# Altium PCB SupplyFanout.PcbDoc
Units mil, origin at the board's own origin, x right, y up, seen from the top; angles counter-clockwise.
Board outline 8000 x 4500 mil, 6 copper layers (Top Layer, Int1 GND, Int2 PWR, Int3 GND, Int4 PWR, Bottom Layer), stack 61.068 mil thick; 132 components, 68 nets, 469 pads, 69 vias.
Unrouted connection lines stored in the file: 26.
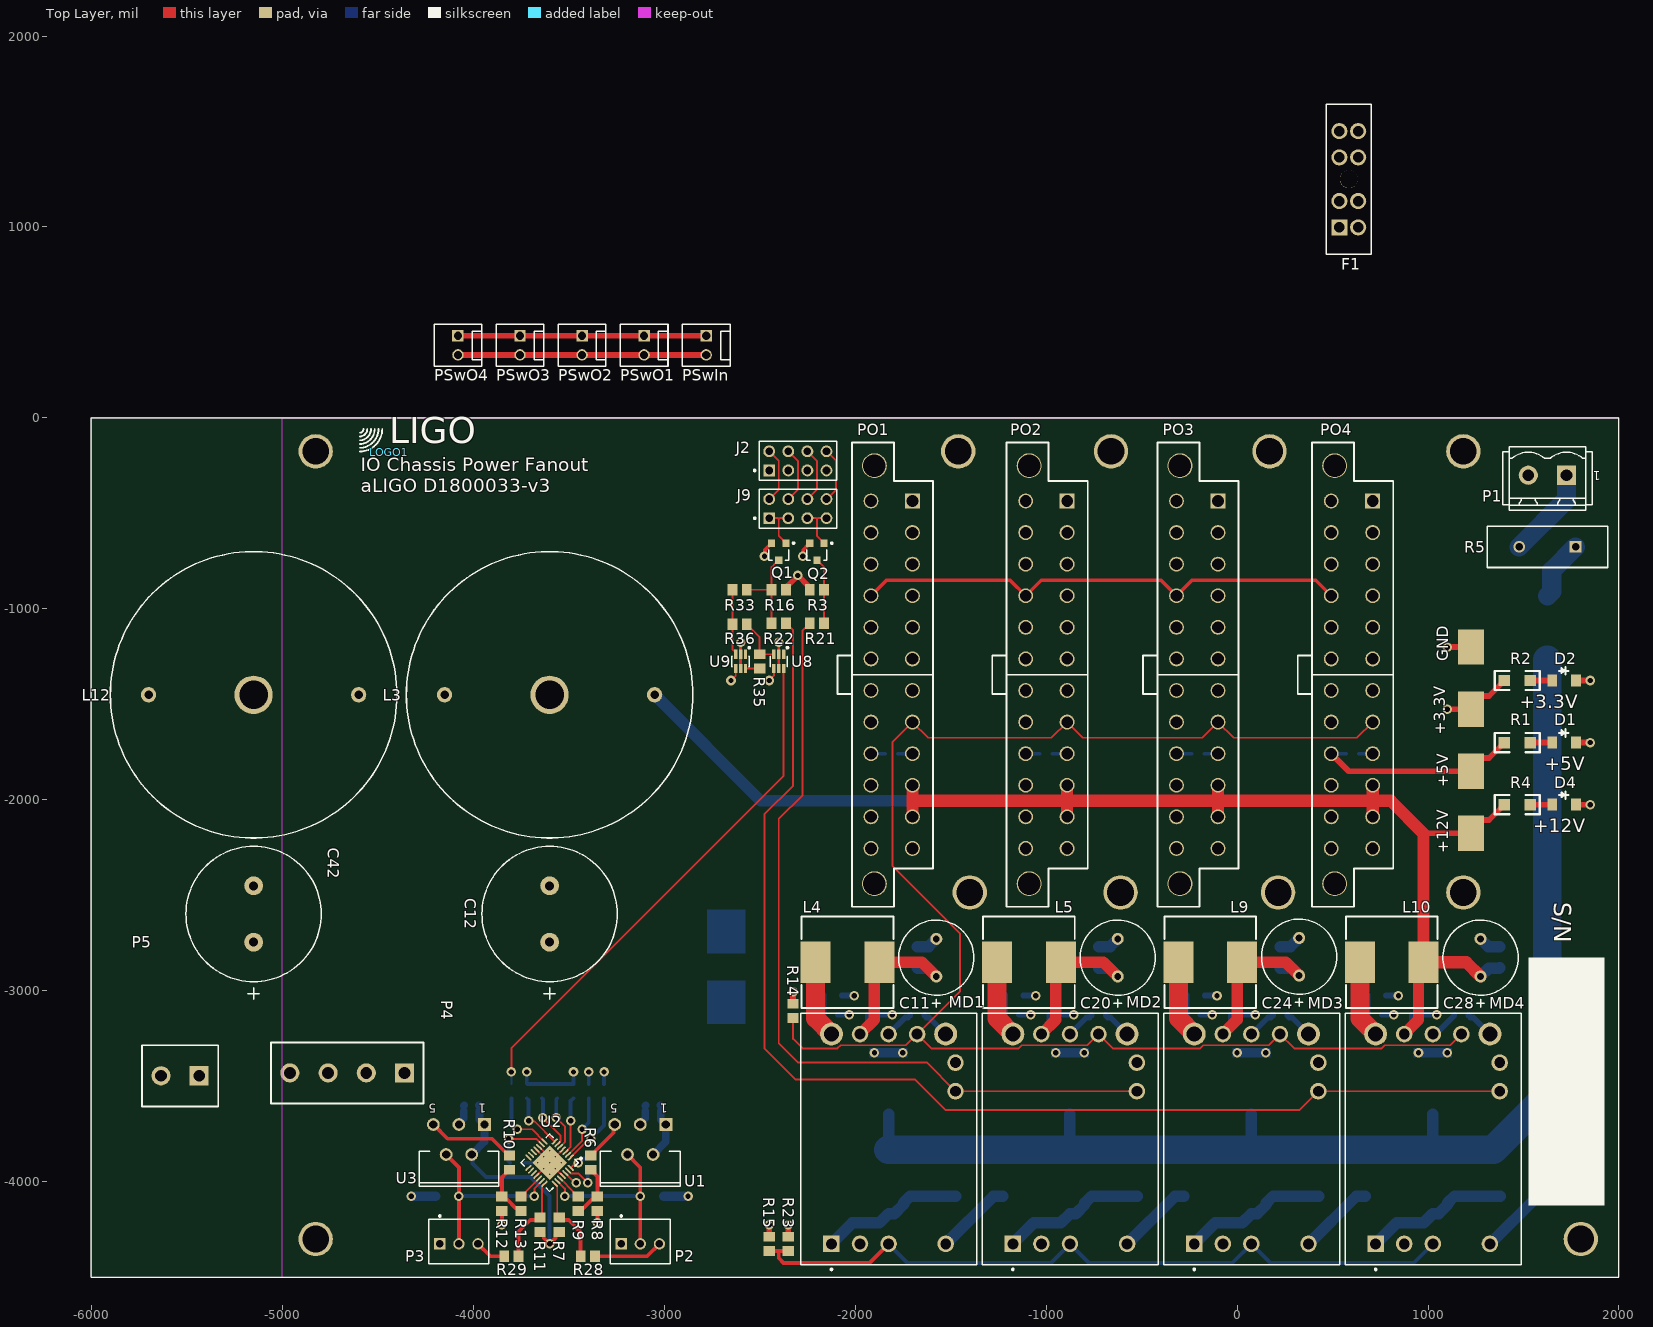
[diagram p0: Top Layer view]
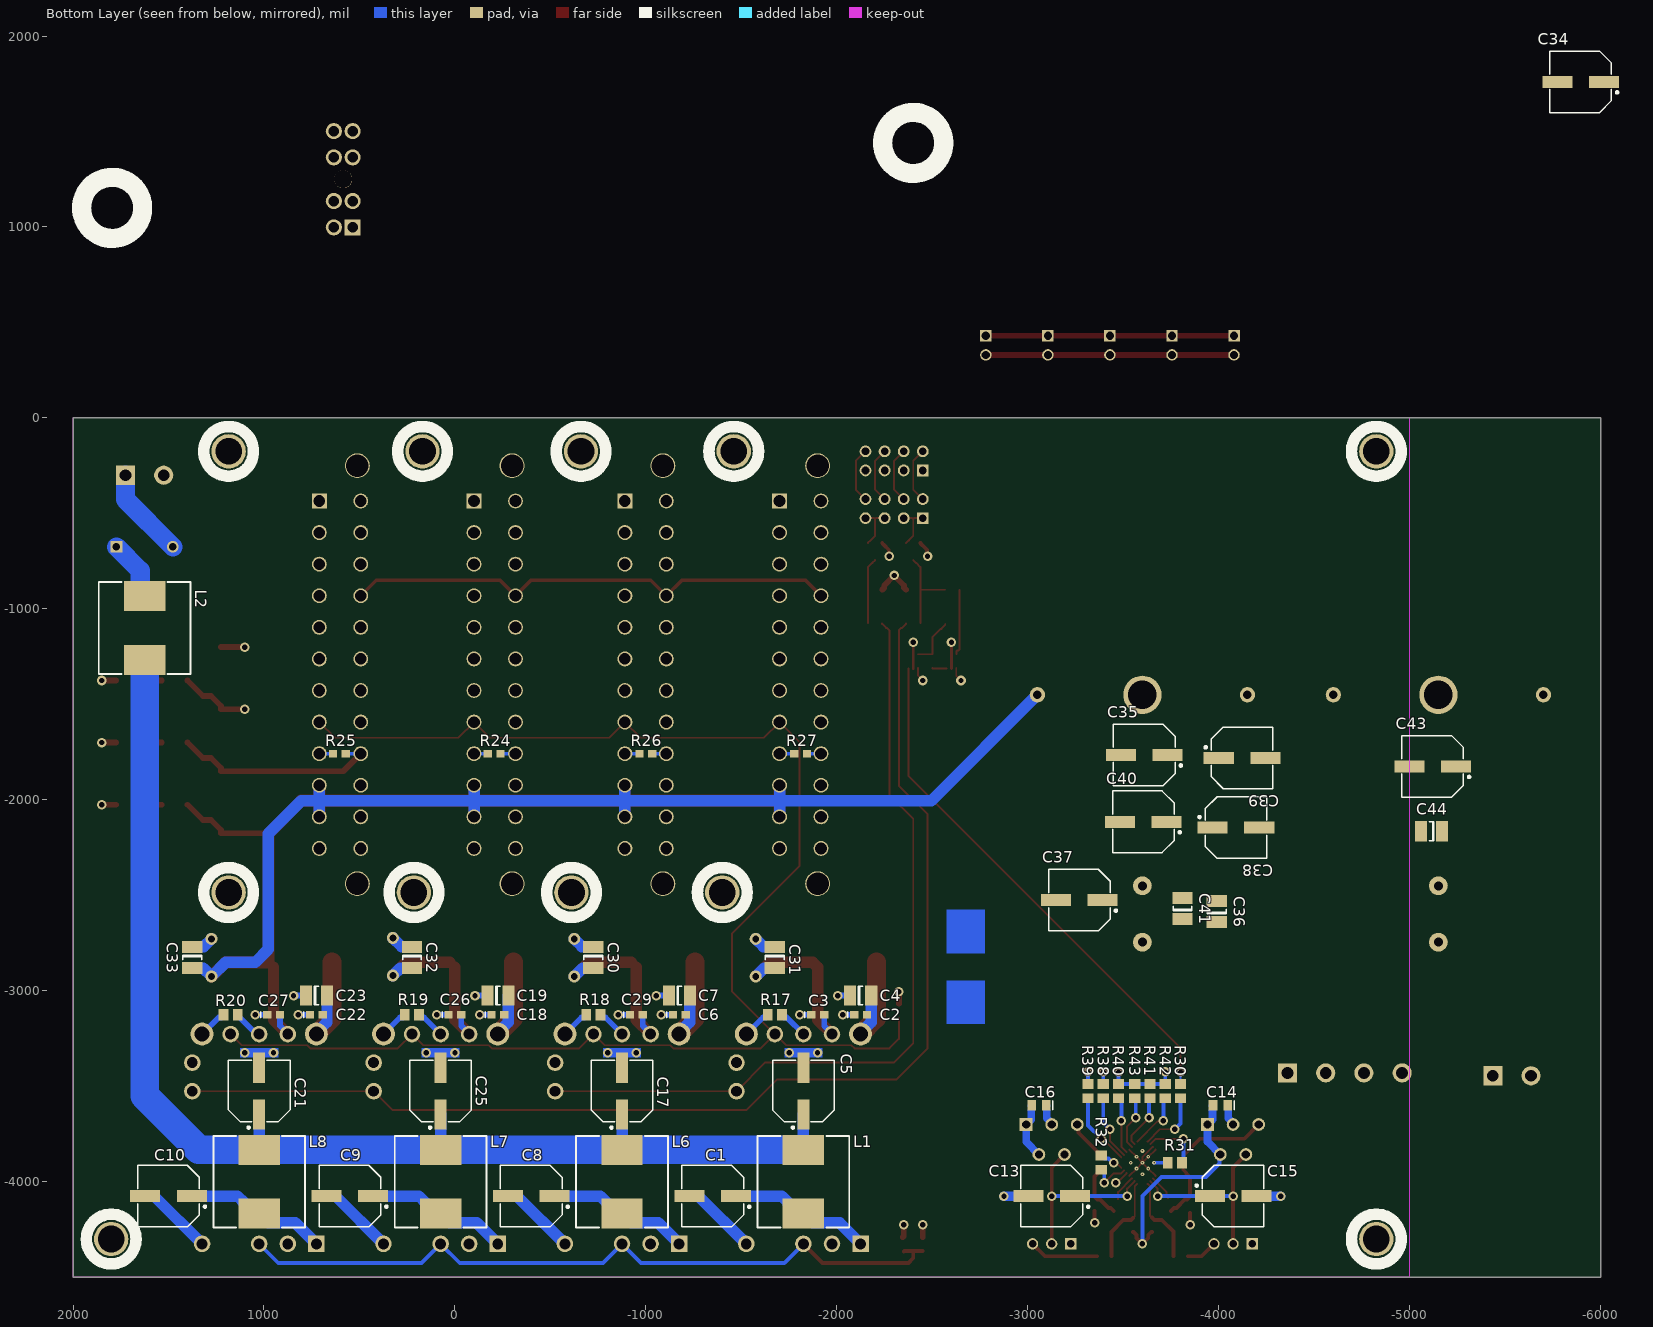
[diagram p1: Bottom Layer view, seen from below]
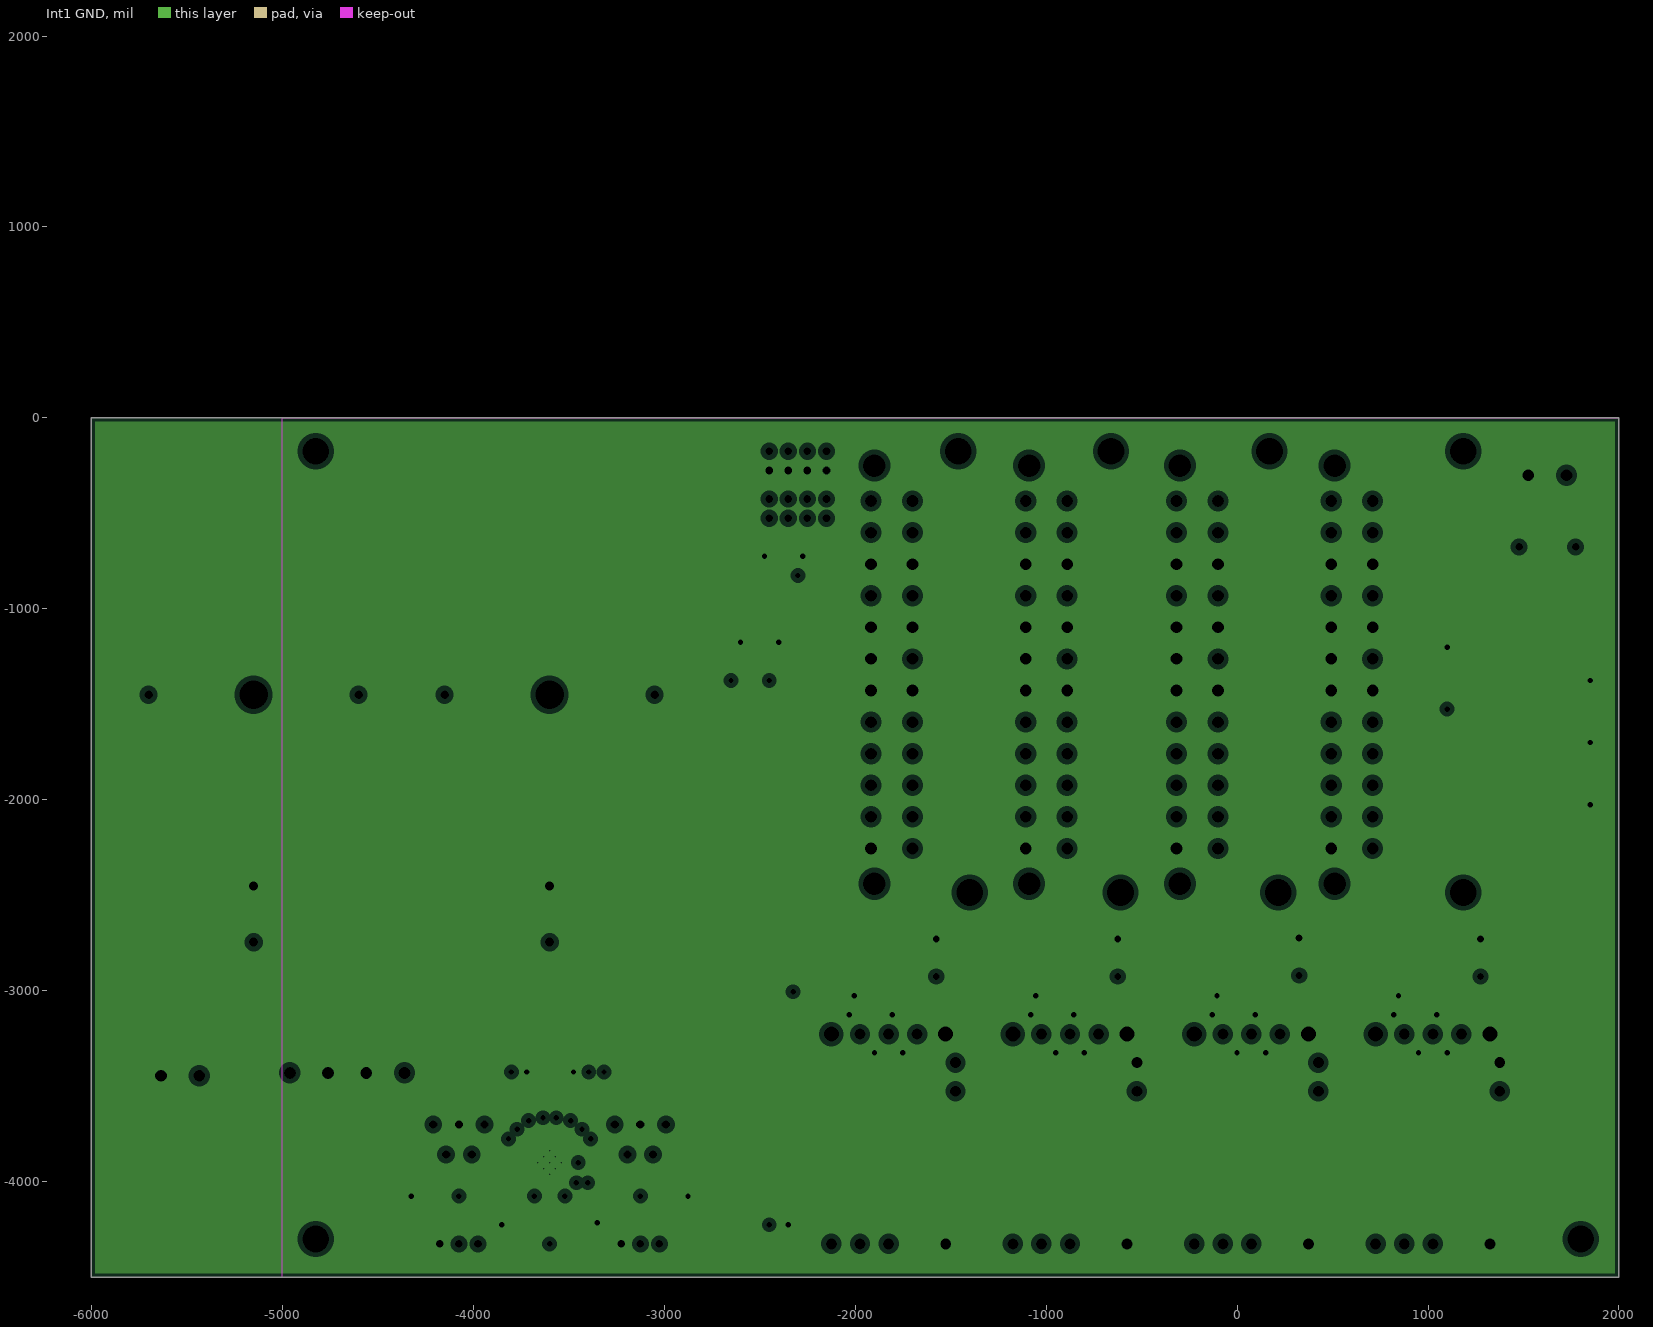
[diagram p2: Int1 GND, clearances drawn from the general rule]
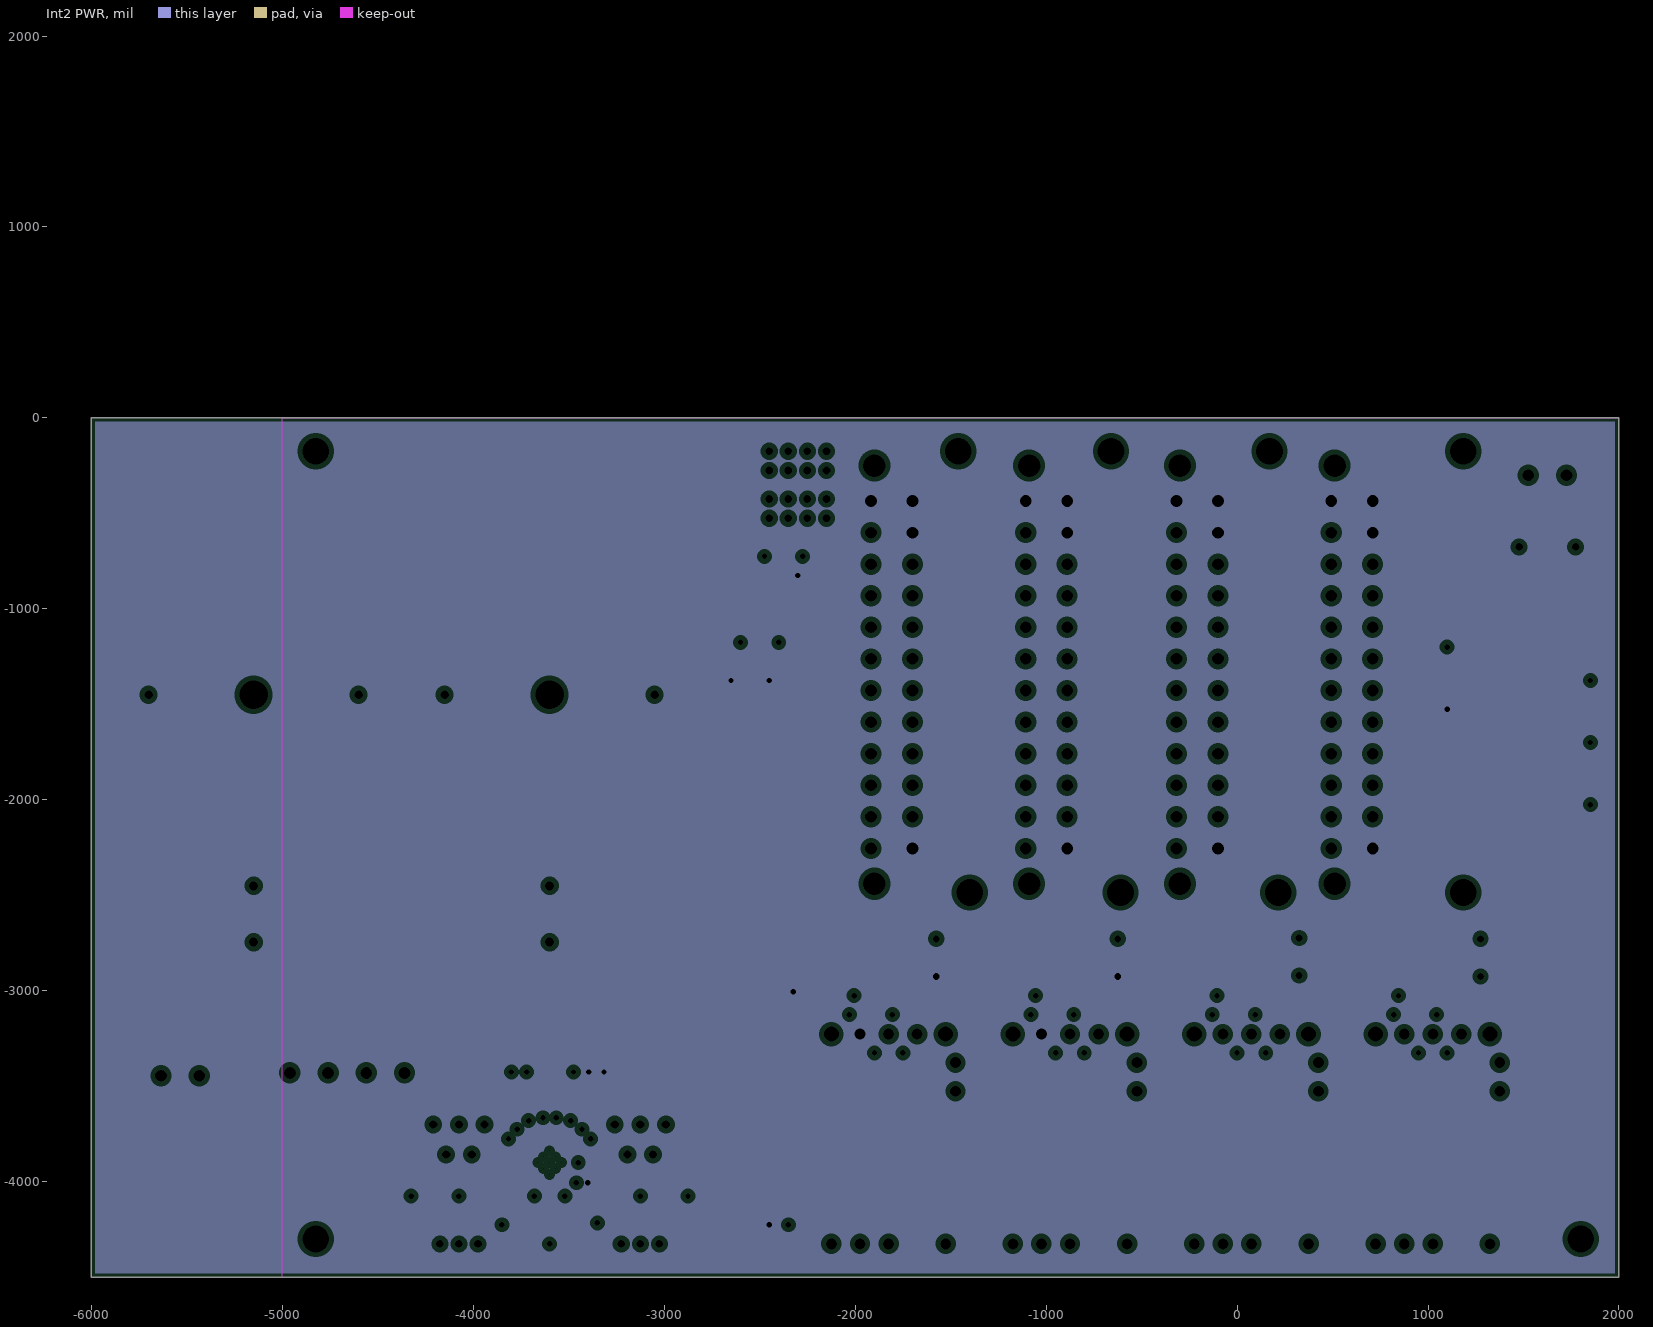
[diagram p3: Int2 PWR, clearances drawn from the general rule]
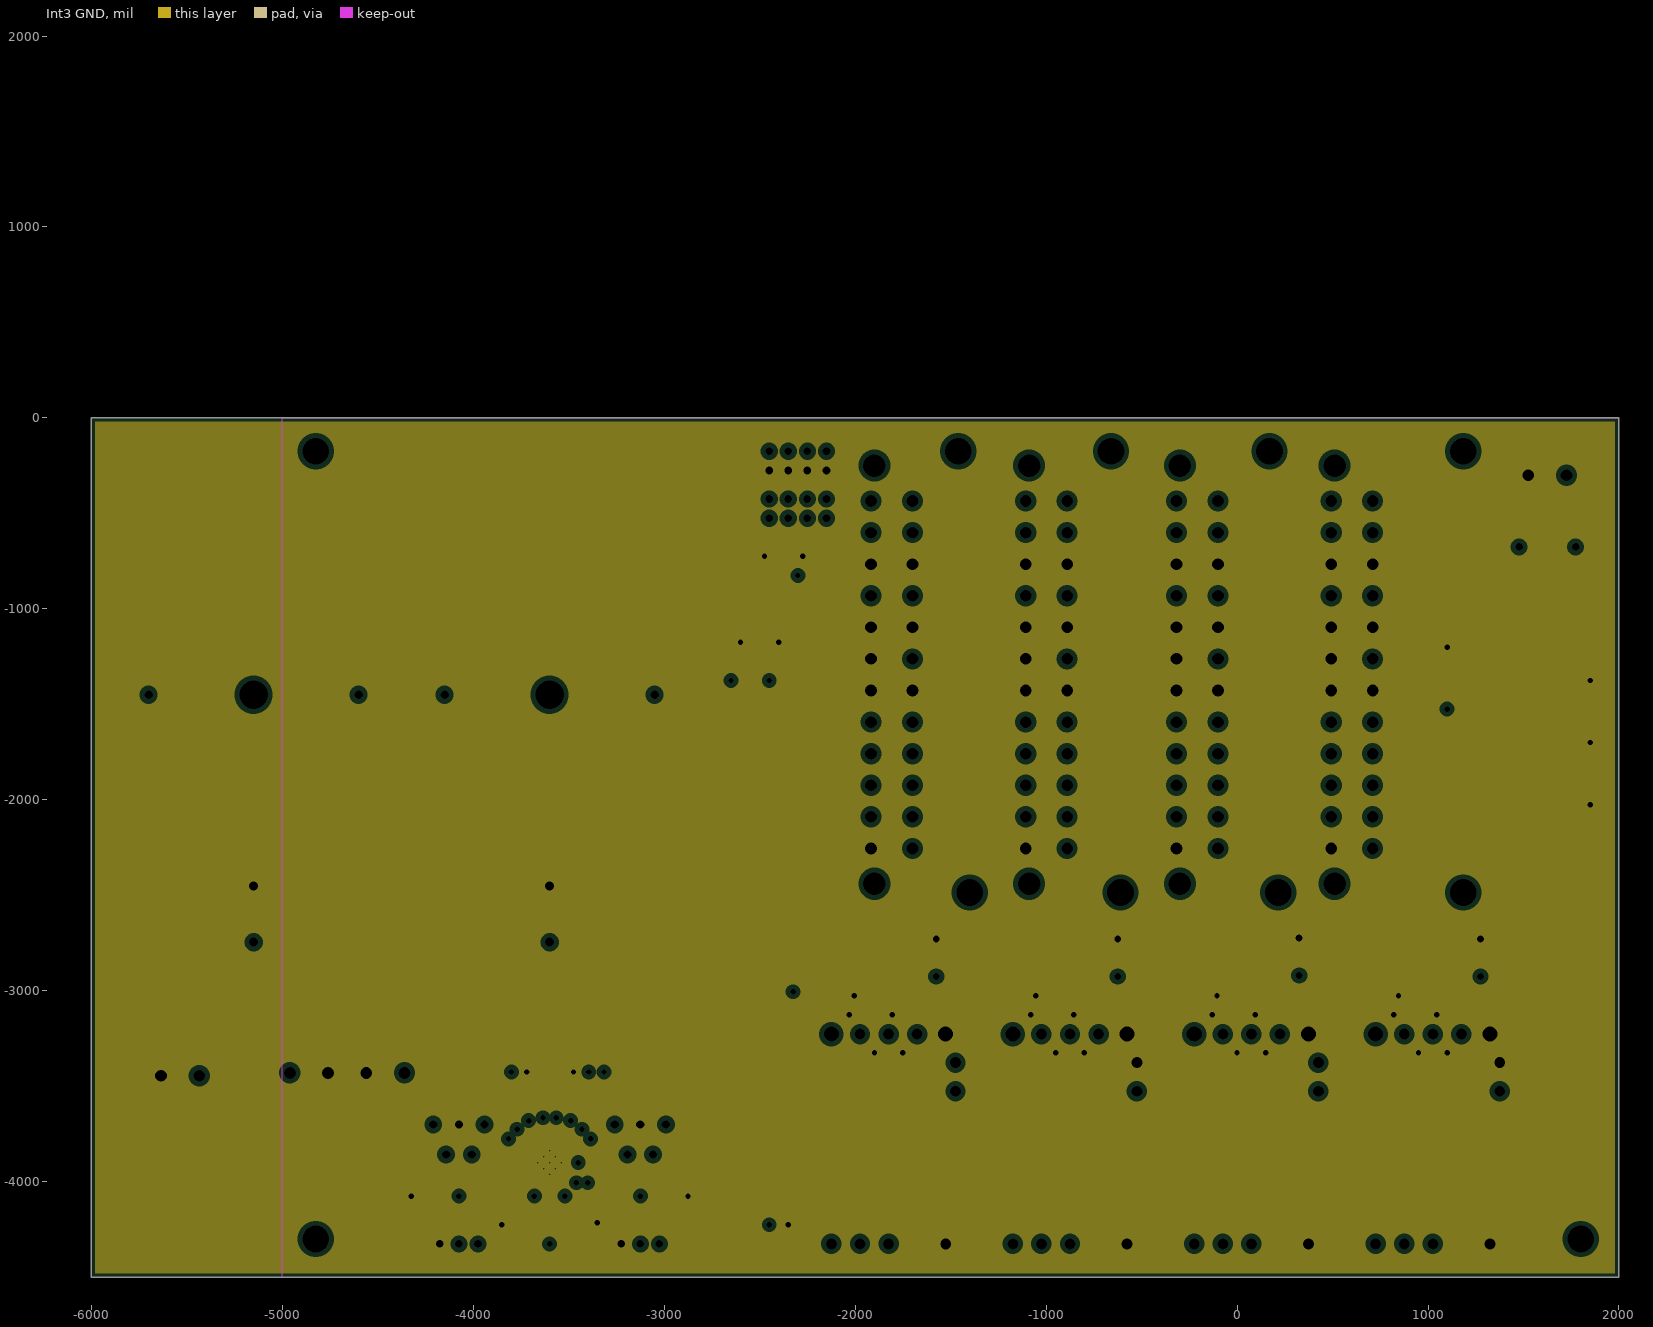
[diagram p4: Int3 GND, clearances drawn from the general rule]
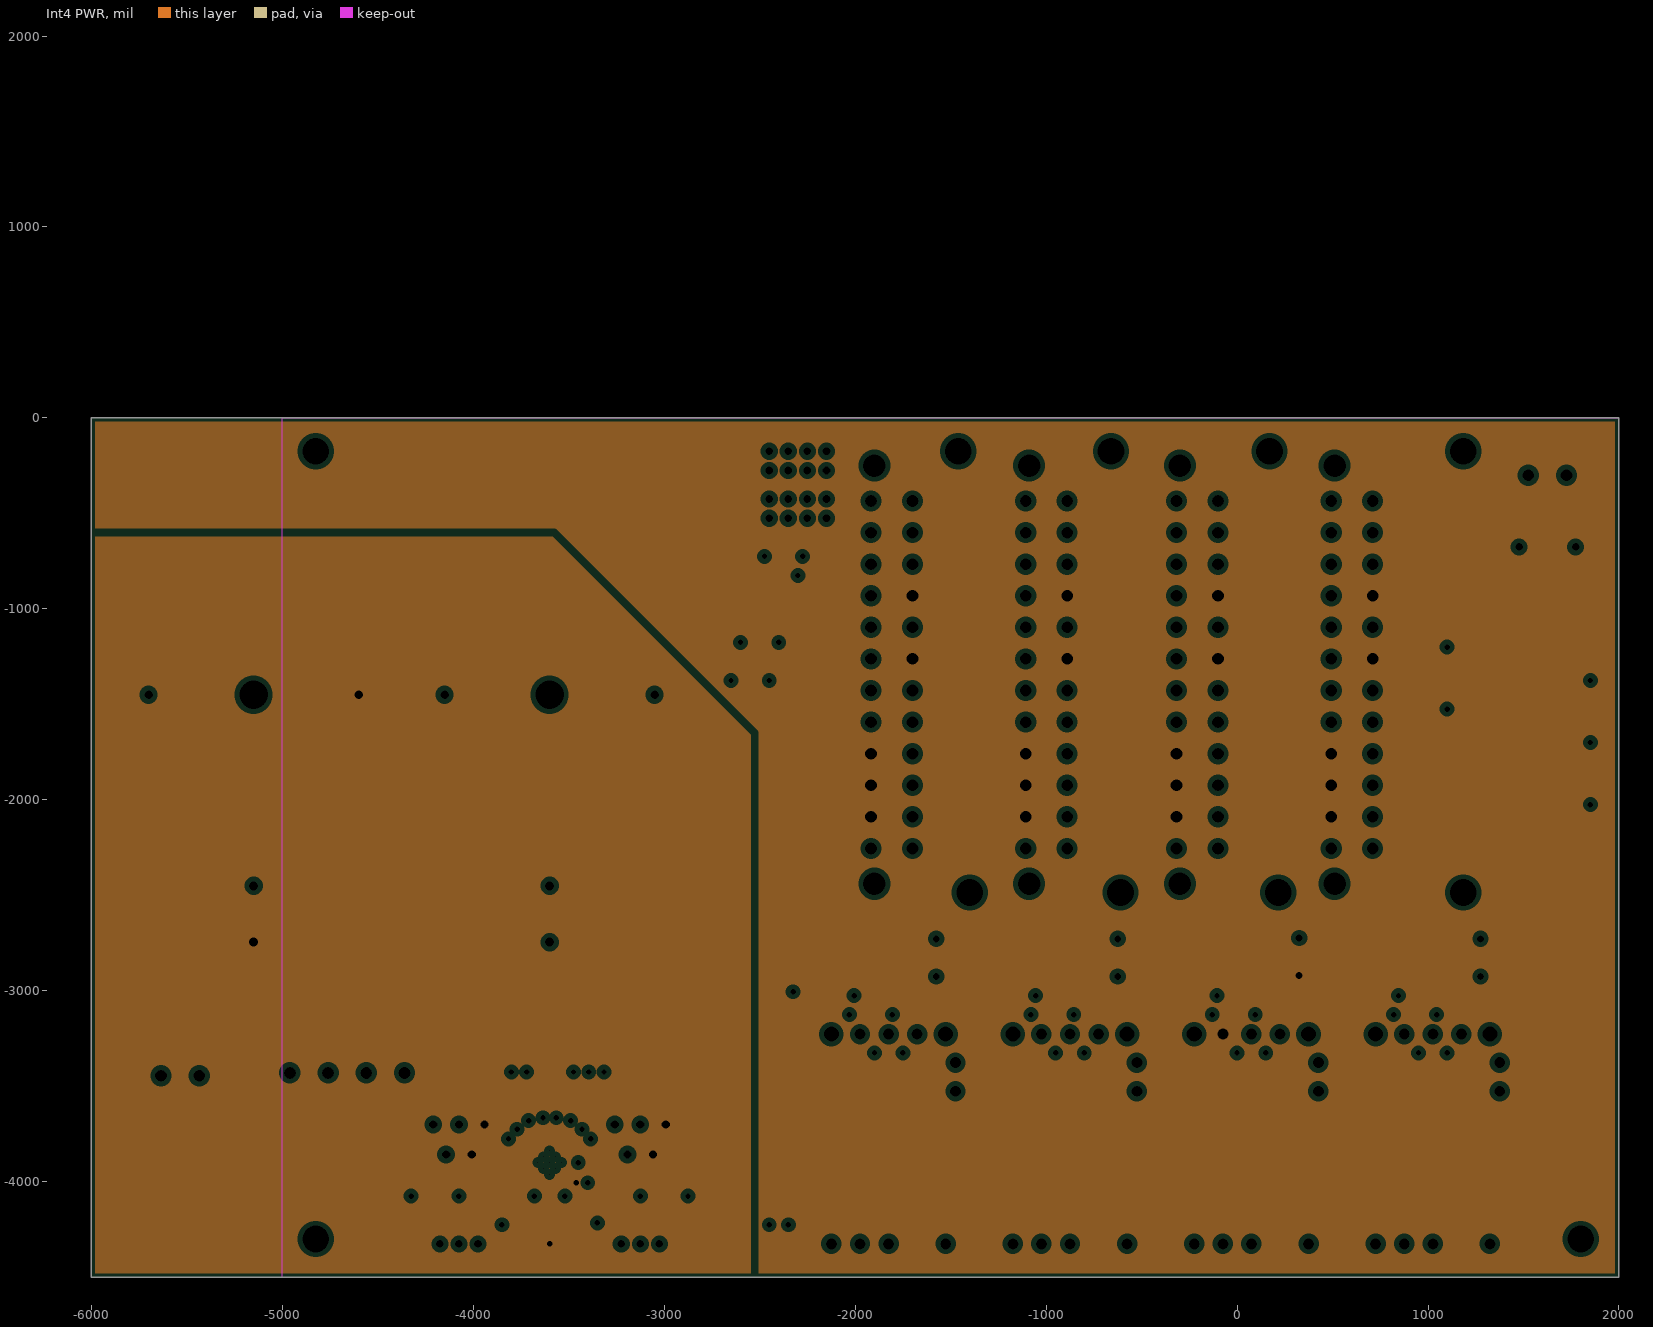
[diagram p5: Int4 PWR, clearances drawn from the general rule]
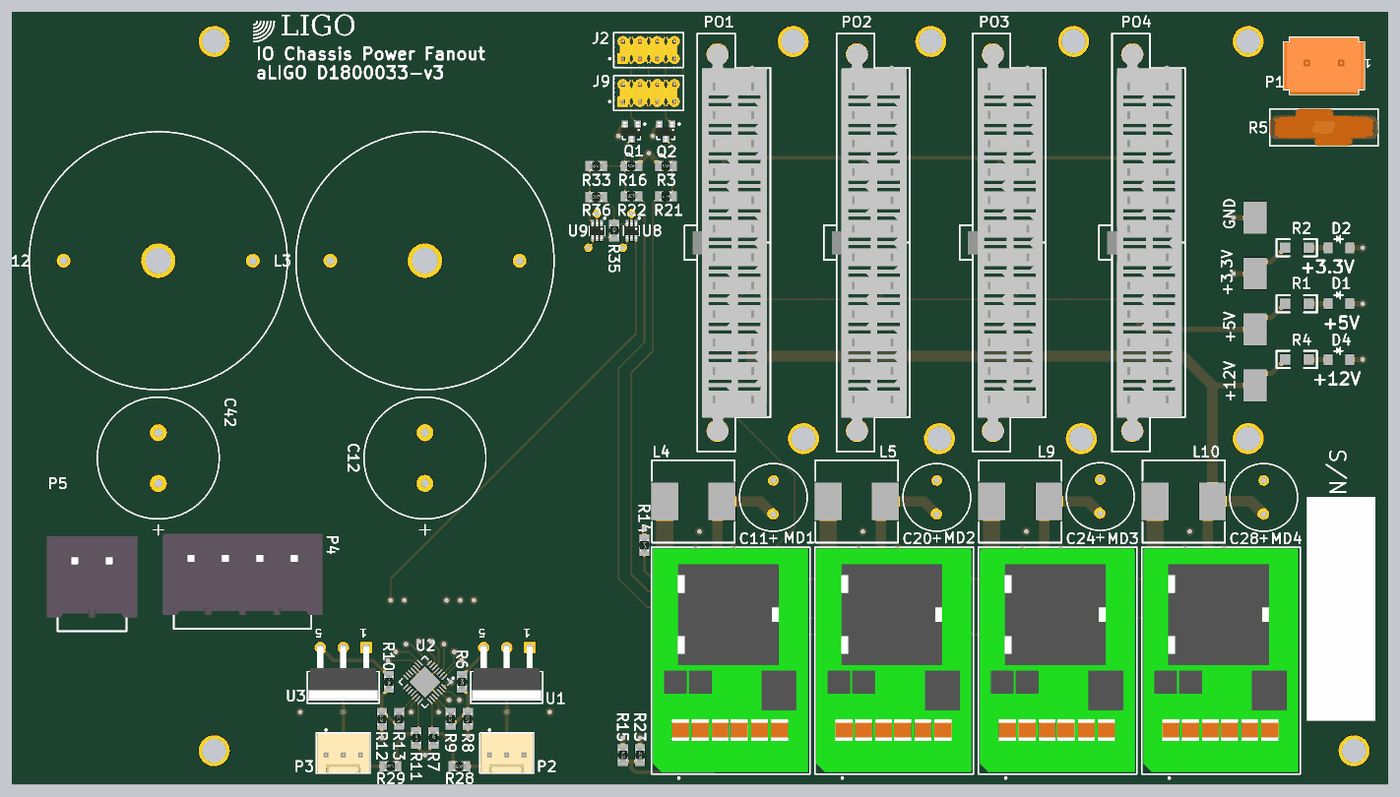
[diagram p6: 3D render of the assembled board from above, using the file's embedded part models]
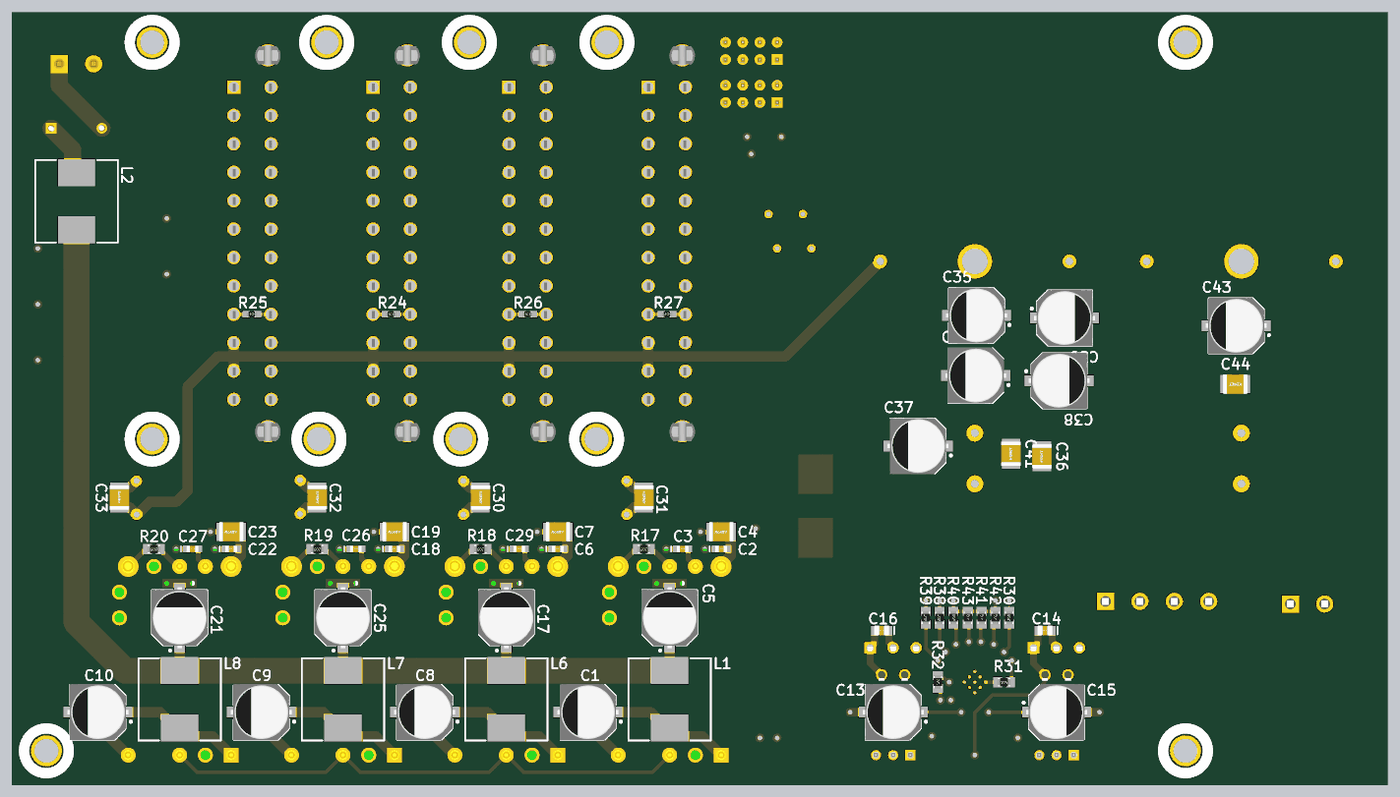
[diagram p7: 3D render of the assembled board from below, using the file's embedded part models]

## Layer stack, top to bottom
Top Solder: solder mask 1, SM-001, Dk 4
Top Layer: signal copper 1.378
Dielectric 1: prepreg 2.8, PP-006, Dk 4.1
Dielectric 2: prepreg 2.8, PP-006, Dk 4.1
Int1 GND: plane copper 1.378, net GND
Dielectric 3: core 18, Core-035, Dk 4.7
Int2 PWR: plane copper 1.378, net +3.3V
Dielectric 4: prepreg 2.8, PP-006, Dk 4.1
Dielectric 5: prepreg 2.8, PP-006, Dk 4.1
Int3 GND: plane copper 1.378, net GND
Dielectric 6: core 18, Core-035, Dk 4.7
Int4 PWR: plane copper 1.378, net (Multiple Nets)
Dielectric 7: prepreg 2.8, PP-006, Dk 4.1
Dielectric 8: prepreg 2.8, PP-006, Dk 4.1
Bottom Layer: signal copper 1.378
Bottom Solder: solder mask 1, SM-001, Dk 4

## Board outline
-6000,-4500 -6000,0 2000,0 2000,-4500

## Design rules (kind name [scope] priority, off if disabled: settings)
Clearance MyBigClearance [InNamedPolygon('Ground')] p1: gap=25 ignorepadtopadclearanceinfootprint=FALSE
Clearance [All] p2: gap=7 ignorepadtopadclearanceinfootprint=FALSE except(0: Arc-Hole Track-Hole SMDPad-Hole THPad-Hole Via-Hole Fill-Hole Poly-Hole Region-Hole Text-Hole)
ComponentClearance [All] p1: gap=500 collisioncheckmode=3 verticalgap=100000 showdistances=FALSE
Height [All] p1: minheight=0 maxheight=2500 prefheight=500
HoleSize [All] p1: absolutevalues=TRUE maxlimit=1000 minlimit=1 maxpercent=80.000 minpercent=20.000
HoleToHoleClearance [All] p1: gap=8 allowstackedmicrovias=TRUE
MinimumSolderMaskSliver [All] p1: minsoldermaskwidth=1
PlaneClearance [All] p1: clearance=25
PlaneConnect [All] p1: planeconnectstyle=Relief reliefexpansion=20 reliefentries=4 reliefconductorwidth=20 reliefairgap=10
PolygonConnect [All] p1: connectstyle=Relief reliefconductorwidth=20 reliefentries=4 polygonreliefangle="90 Angle" airgapwidth=10
RoomDefinition SupplyFanout1 [InComponentClass('SupplyFanout1')] p1: confinementstyle=ConfineIn formatcopy=TRUE lockcomponents=FALSE outline -7715,-5250 2085,-5250 2085,635 -7715,635
RoomDefinition SupplyFanout3 [InComponentClass('SupplyFanout3')] p2: confinementstyle=ConfineIn formatcopy=TRUE lockcomponents=FALSE outline -7915,-5445 2260,-5445 2260,875 -7915,875
RoomDefinition SupplyFanout2 [InComponentClass('SupplyFanout2')] p3: confinementstyle=ConfineIn formatcopy=TRUE lockcomponents=FALSE outline -7815,-5370 2190,-5370 2190,755 -7815,755
RoutingVias [All] p1: holewidth=28 width=50 viastyle="Through Hole" minholewidth=28 minwidth=50 maxholewidth=28 maxwidth=50
SilkToSilkClearance [All] p1: silktosilkclearance=2
SilkToSolderMaskClearance [IsPad] p1: minsilkscreentomaskgap=0.1 clearancetoexposedcopper=TRUE
SolderMaskExpansion [All] p1: expansion=4 istentingtop=FALSE
Width [All] p1: maxlimit=200 minlimit=10 preferedwidth=20
21 further rules are at their usual default settings.

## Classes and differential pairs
component class SupplyFanout3: C12 C13 C14 C15 C16 C34 C35 C36 C37 C38 C39 C40 C41 C42 C43 C44 F1 L3 L12 P2 P3 R6 R7 R8 R9 R10 R11 R12 R13 R28 R29 R30 R31 R32 R35 R36 R38 R39 R40 R41 R42 R43 U1 U2 U3 U8 U9
component class SupplyFanout1: C1 C2 C3 C4 C5 C6 C7 C8 C9 C10 C11 C17 C18 C19 C20 C21 C22 C23 C24 C25 C26 C27 C28 C29 C30 C31 C32 C33 J2 J9 L1 L2 L4 L5 L6 L7 L8 L9 L10 LOGO1 MD1 MD2 MD3 MD4 P1 P4 P5 Q1 Q2 R3 R5 R14 R15 R16 R17 R18 R19 R20 R21 R22 R23 R33
component class SupplyFanout2: +3.3V +5V +12V D1 D2 D4 GND PO1 PO2 PO3 PO4 PSwIn PSwO1 PSwO2 PSwO3 PSwO4 R1 R2 R4 R24 R25 R26 R27

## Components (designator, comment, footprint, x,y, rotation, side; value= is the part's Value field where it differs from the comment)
+3.3V "TESTPT" SMT_TP 1225,-1525 r270 top
+5V "TESTPT" SMT_TP 1225,-1850 r270 top
+12V "TESTPT" SMT_TP 1225,-2175 r270 top
C1 "100uF" AC083-033/E -1350,-4075 r0 bottom
C2 "0.1uF" CC1608-0603 -2125,-3125 r180 bottom
C3 "0.1uF" CC1608-0603 -1900,-3125 r180 bottom
C4 "22uF" CC3225-1210 -2125,-3025 r180 bottom
C5 "300uF" AC083-033/E -1825,-3525 r90 bottom
C6 "0.1uF" CC1608-0603 -1175,-3125 r180 bottom
C7 "22uF" CC3225-1210 -1175,-3025 r180 bottom
C8 "100uF" AC083-033/E -400,-4075 r0 bottom
C9 "100uF" AC083-033/E 550,-4075 r0 bottom
C10 "100uF" AC083-033/E 1500,-4075 r0 bottom
C11 "220uF" RB10/5.0 -1575,-2925 r90 top
C12 "5700uF" RB18/7.5 -3600,-2745.28 r90 top
C13 "47uF" AC083-033/E -3125,-4075 r0 bottom
C14 "0.33uF" CC2013-0805 -4008.07,-3600 r0 bottom
C15 "47uF" AC083-033/E -4075,-4075 r180 bottom
C16 "0.33uF" CC2013-0805 -3058.07,-3600 r0 bottom
C17 "300uF" AC083-033/E -875,-3525 r90 bottom
C18 "0.1uF" CC1608-0603 -225,-3125 r180 bottom
C19 "22uF" CC3225-1210 -225,-3025 r180 bottom
C20 "220uF" RB10/5.0 -625,-2925 r90 top
C21 "300uF" AC083-033/E 1025,-3525 r90 bottom
C22 "0.1uF" CC1608-0603 725,-3125 r180 bottom
C23 "22uF" CC3225-1210 725,-3025 r180 bottom
C24 "220uF" RB10/5.0 325,-2920 r90 top
C25 "300uF" AC083-033/E 75,-3525 r90 bottom
C26 "0.1uF" CC1608-0603 0,-3125 r180 bottom
C27 "0.1uF" CC1608-0603 950,-3125 r180 bottom
C28 "220uF" RB10/5.0 1275,-2925 r90 top
C29 "0.1uF" CC1608-0603 -950,-3125 r180 bottom
C30 "22uF" CC3225-1210 -725,-2825 r270 bottom
C31 "22uF" CC3225-1210 -1675,-2825 r270 bottom
C32 "22uF" CC3225-1210 225,-2825 r270 bottom
C33 "22uF" CC3225-1210 1375.4,-2825 r270 bottom
C34 "100uF" AC083-033/E -5895,1760 r0 bottom
C35 "100uF" AC083-033/E -3610,-1765 r0 bottom
C36 "22uF" CC3225-1210 -3990,-2585 r90 bottom
C37 "100uF" AC083-033/E -3270,-2525 r0 bottom
C38 "100uF" AC083-033/E -4090,-2145 r180 bottom
C39 "100uF" AC083-033/E -4122.05,-1780 r180 bottom
C40 "100uF" AC083-033/E -3605,-2115 r0 bottom
C41 "22uF" CC3225-1210 -3810,-2569.88 r90 bottom
C42 "5700uF" RB18/7.5 -5150,-2745.28 r90 top
C43 "100uF" AC083-033/E -5120,-1825 r0 bottom
C44 "22uF" CC3225-1210 -5114.88,-2165 r0 bottom
D1 "LED2" SMD_LED 1685,-1685 r0 top
D2 "LED2" SMD_LED 1685,-1360 r0 top
D4 "LED2" SMD_LED 1685,-2010 r0 top
F1 "178.6165.0002" FP-178_6165-MFG 585,1250 r90 top
GND "TESTPT" SMT_TP 1225,-1200 r270 top
J2 "HTSW-104-07-G-D" FP-HTSW-104-07-G-D-MFG -2300,-225 r0 top
J9 "HTSW-104-07-G-D" FP-HTSW-104-07-G-D-MFG -2300,-475 r0 top
L1 "1uH" MSS1278 -1825,-4000 r270 bottom
L2 "1uH" MSS1278 1625,-1100 r90 bottom
L3 "15mH" "Rnd Inductor 45D" -3600,-1450 r180 top
L4 "22uH" MSS1278 -2040,-2850 r0 top
L5 "22uH" MSS1278 -1090,-2850 r0 top
L6 "1uH" MSS1278 -875,-4000 r270 bottom
L7 "1uH" MSS1278 75,-4000 r270 bottom
L8 "1uH" MSS1278 1025,-4000 r270 bottom
L9 "47uH" MSS1278 -140,-2850 r0 top
L10 "33uH" MSS1278 810,-2850 r0 top
L12 "15mH" "Rnd Inductor 45D" -5150,-1450 r180 top
LOGO1 "LIGO logo" LIGO-LOGO-SM -4440,-180 r0 top
MD1 "TDK Lambda Sync Power Supply" TDK-Lambda -1376.17,-3128.15 r180 top
MD2 "TDK Lambda Sync Power Supply" TDK-Lambda -426.17,-3128.15 r180 top
MD3 "TDK Lambda Sync Power Supply" TDK-Lambda 523.83,-3128.15 r180 top
MD4 "TDK Lambda Sync Power Supply" TDK-Lambda 1473.83,-3128.15 r180 top
P1 "TBlock_5.08_2" SL_5_08HC_180B_02 1625,-300 r180 top
P2 "61900311121" 61900311121 -3125,-4313.19 r180 top
P3 "61900311121" 61900311121 -4075,-4313.19 r180 top
P4 "TBlock_5.08_4" TBLOCK-5.08-4 -4660,-3430 r180 top
P5 "TBlock_5.08_2" TBLOCK-5.08-2 -5535,-3445 r180 top
PO1 "Header 12X2A" ATX24Pin_M -1700,-435 r180 top
PO2 "Header 12X2A" ATX24Pin_M -890,-435 r180 top
PO3 "Header 12X2A" ATX24Pin_M -100,-435 r180 top
PO4 "Header 12X2A" ATX24Pin_M 710,-435 r180 top
PSwIn "Header 2" Molex100-2V -2780,380 r270 top
PSwO1 "Header 2" Molex100-2V -3105,380 r270 top
PSwO2 "Header 2" Molex100-2V -3430,380 r270 top
PSwO3 "Header 2" Molex100-2V -3755,380 r270 top
PSwO4 "Header 2" Molex100-2V -4080,380 r270 top
Q1 "FDV301N" SO-G3/C2.25 -2400,-700 r180 top
Q2 "FDV301N" SO-G3/C2.25 -2200,-700 r180 top
R1 "500" 1206 1535,-1700 r180 top
R2 "249" 1206 1535,-1375 r180 top
R3 "10k" CR2012-0805 -2200,-900 r0 top
R4 "1k" 1206 1400,-2025 r0 top value=1K
R5 "NTPAD160LDNB0" FP-NTPAD-MFG 1625,-675 r180 top
R6 "2.4k" CR2012-0805 -3385,-3900 r270 top
R7 "1.00K" CR2012-0805 -3550,-4225 r270 top
R8 "27k" CR2012-0805 -3350,-4115 r90 top
R9 "470" CR2012-0805 -3450,-4115 r90 top
R10 "2.4k" CR2012-0805 -3810,-3900 r270 top
R11 "1.00K" CR2012-0805 -3650,-4225 r270 top
R12 "27k" CR2012-0805 -3850,-4115 r90 top
R13 "470" CR2012-0805 -3750,-4115 r90 top
R14 "10k" CR2012-0805 -2325,-3105 r270 top
R15 "NS" CR2012-0805 -2450,-4325 r270 top
R16 "10k" CR2012-0805 -2400,-900 r0 top
R17 "30.3k" CR2012-0805 -1675,-3125 r0 bottom
R18 "30.3k" CR2012-0805 -725,-3125 r0 bottom
R19 "8.57k" CR2012-0805 225,-3125 r0 bottom
R20 "1.82k" CR2012-0805 1175,-3125 r0 bottom
R21 "5k" CR2012-0805 -2200,-1075 r180 top
R22 "5k" CR2012-0805 -2400,-1075 r0 top
R23 "10k" CR2012-0805 -2350,-4325 r270 top
R24 "0" CR1608-0603 -205,-1758.2 r0 bottom
R25 "0" CR1608-0603 605,-1758.2 r0 bottom
R26 "0" CR1608-0603 -1000,-1758.2 r0 bottom
R27 "0" CR1608-0603 -1810,-1758.2 r0 bottom
R28 "0" CR2012-0805 -3400,-4390 r180 top
R29 "0" CR2012-0805 -3800,-4390 r0 top
R30 "0" CR2012-0805 -3800,-3525 r90 bottom
R31 "0" CR2012-0805 -3770,-3900 r0 bottom
R32 "10k" CR2012-0805 -3385,-3900 r270 bottom
R33 "5k" CR2012-0805 -2605,-900 r180 top
R35 "0" CR2012-0805 -2500,-1275 r270 top
R36 "0" CR2012-0805 -2605,-1080 r0 top
R38 "4.7k" CR2012-0805 -3395,-3525 r90 bottom
R39 "4.7k" CR2012-0805 -3315,-3525 r90 bottom
R40 "10k" CR2012-0805 -3475,-3525 r270 bottom
R41 "10k" CR2012-0805 -3640,-3525 r270 bottom
R42 "10k" CR2012-0805 -3720,-3525 r270 bottom
R43 "10k" CR2012-0805 -3560,-3525 r270 bottom
U1 "LT1963A" TO-220-5B -3125,-3778.74 r180 top
U2 "MAX6620ATI+" MAXM-T2855+8_M -3600,-3900 r225 top
U3 "LT1963A" TO-220-5B -4075,-3778.74 r180 top
U8 "PE3513" SC70 -2400,-1275 r180 top
U9 "PE3511" SC70 -2600,-1275 r180 top

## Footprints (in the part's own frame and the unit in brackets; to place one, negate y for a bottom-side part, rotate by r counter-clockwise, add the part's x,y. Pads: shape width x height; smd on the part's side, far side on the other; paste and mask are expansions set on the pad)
1206 [mil]
  rect 60x60 smd: 1(0,0) 2(135,0)
  silkscreen extent -50,-50 185,50
61900311121 [mm] "2.54mm Male Locking Header, 3p"
  rect 1.5x1.5 hole 1: 1(2.54,0.3)
  round 1.5 hole 1: 2(0,0.3) 3(-2.54,0.3)
  silkscreen extent -3.98,-3.52 3.98,2.98, body extent -3.81,-2.9 3.81,2.9, height 11.53
AC083-033/E [mm] "SMT Electrolyte Capacitor; E Size, Body 8.3 x 8.3 mm (LxW typ)"
  rect 4x1.6 smd: 1(-3.1,0) 2(3.1,0)
  silkscreen extent -5,-4.1 4.1,4.1, body extent -4.5,-4.15 4.5,4.15, height 6.2
ATX24Pin_M [mil] "ATX 24 pin header male, power, 4.2mm"
  rect 78x78 hole 61: 1(0,0)
  round 78 hole 61: 2(0,165.4) 3(0,330.8) 4(0,496.2) 5(0,661.6) 6(0,827) 7(0,992.4) 8(0,1157.8) 9(0,1323.2) 10(0,1488.6) 11(0,1654) 12(0,1819.4) 13(217,0) 14(217,165.4) 15(217,330.8) 16(217,496.2) 17(217,661.6) 18(217,827) 19(217,992.4) 20(217,1157.8) 21(217,1323.2) 22(217,1488.6) 23(217,1654) 24(217,1819.4)
  round 130 hole 118: 25(199,-184.8) 26(199,2004.2)
  silkscreen extent -108,-305 392,2125, body extent -89,-237 344,2061, height 504
CC1608-0603 [mm] "Chip Capacitor; Body 1.6 x 0.8 mm (LxW typ)"
  rect 1.1x1 smd: 1(-0.85,0) 2(0.85,0)
  silkscreen extent -1.7,-0.4 -1.7,0.4, body extent -0.88,-0.48 0.87,0.47, height 0.87
CC2013-0805 [mm] "Chip Capacitor; Body 2.0 x 1.3 mm (LxW typ)"
  rect 1.15x1.4 smd: 1(-0.975,0) 2(0.975,0)
  silkscreen extent -1.85,-0.6 -1.85,0.6, body extent -1.1,-0.73 1.1,0.72, height 0.88
CC3225-1210 [mm] "Chip Capacitor; Body 3.2 x 2.5 mm (LxW typ)"
  rect 1.6x2.7 smd: 1(-1.4,0) 2(1.4,0)
  silkscreen extent -0.3,-1.25 0.3,1.25, body extent -1.85,-1.45 1.85,1.45, height 1.4
CR1608-0603 [mm] "Chip Resistor; Body 1.6 x 0.8 mm (LxW typ)"
  rect 1.1x1 smd: 1(-0.85,0) 2(0.85,0)
  body extent -0.76,-0.43 0.79,0.42, height 0.46
CR2012-0805 [mm] "Chip Resistor; Body 2.0 x 1.3 mm (LxW typ)"
  rect 1.3x1.5 smd: 1(-0.95,0) 2(0.95,0)
  body extent -1,-0.62 1,0.63, height 0.46
FP-178_6165-MFG [mm]
  round 2.15 hole 1.4 paste-1000 mask+0: 1(-6.4,-1.25) 1(-2.9,-1.25) 1(-2.9,1.25) 2(2.9,-1.25) 2(2.9,1.25) 2(6.4,-1.25) 2(6.4,1.25)
  rect 2.15x2.15 hole 1.4 paste-1000 mask+0: 1(-6.4,1.25)
  round 2.4 hole 2.4 unplated paste-1000 mask+0: ""(0,0)
  silkscreen extent -10,-3 10,3, body extent -10.1,-3.1 10.1,3.1, height 0.25
FP-HTSW-104-07-G-D-MFG [mm]
  rect 1.57x1.57 hole 1.02 paste-1000 mask+0: 1(-3.81,-1.27)
  round 1.57 hole 1.02 paste-1000 mask+0: 2(-3.81,1.27) 3(-1.27,-1.27) 4(-1.27,1.27) 5(1.27,-1.27) 6(1.27,1.27) 7(3.81,-1.27) 8(3.81,1.27)
  silkscreen extent -5.87,-2.58 5.14,2.58, body extent -5.24,-2.68 5.24,2.68, height 0.25
FP-NTPAD-MFG [mm]
  rect 1.55x1.55 hole 1 paste-1000 mask+0: 1(-3.75,0)
  round 1.55 hole 1 paste-1000 mask+0: 2(3.75,0)
  silkscreen extent -8,-2.75 8,2.75, body extent -8.1,-2.85 8.1,2.85, height 0.25
LIGO-LOGO-SM [mil] "Smaller Ligo Logo"
  silkscreen extent -154,4 -36,122
MAXM-T2855+8_M [mm] "QFN, 28-Leads, Body 5x5mm, Pitch 0.5mm, Thermal Pad 3.25x3.25mm, IPC Low Density"
  oval 1.05x0.25 smd: 1(-2.475,1.5) 2(-2.475,1) 3(-2.475,0.5) 4(-2.475,0) 5(-2.475,-0.5) 6(-2.475,-1) 7(-2.475,-1.5) 15(2.475,-1.5) 16(2.475,-1) 17(2.475,-0.5) 18(2.475,0) 19(2.475,0.5) 20(2.475,1) 21(2.475,1.5)
  oval 0.25x1.05 smd: 8(-1.5,-2.475) 9(-1,-2.475) 10(-0.5,-2.475) 11(0,-2.475) 12(0.5,-2.475) 13(1,-2.475) 14(1.5,-2.475) 22(1.5,2.475) 23(1,2.475) 24(0.5,2.475) 25(0,2.475) 26(-0.5,2.475) 27(-1,2.475) 28(-1.5,2.475)
  rect 3.25x3.25 smd: 29(0,0)
  silkscreen extent -3.47,-2.7 2.7,2.7, body extent -2.55,-2.55 2.55,2.55, height 0.8
Molex100-2V [mil] "Footprint for 2-pin 0.1\" pitch Molex Vertical connector."
  rect 60x60 hole 43: 1(-50,0)
  round 60 hole 43: 2(50,0)
  silkscreen extent -110,-125 110,125
MSS1278 [mil] "Power Inductor, MSS1278 series, Coilcraft"
  rect 157x217 smd: 1(-167,0) 2(167,0)
  silkscreen extent -240,-240 240,240
RB10/5.0 [mm] "Electrolyte, radial, 10mm diameter"
  round 1.6 hole 0.9: 1(0,0) 2(5,0)
  silkscreen extent -4.06,-5 7.5,5
RB18/7.5 [mm] "Electrolyte, radial, 18mm diameter"
  round 2.5 hole 1.2: 1(0,0) 2(7.5,0)
  silkscreen extent -7.62,-9 12.75,9
"Rnd Inductor 45D" [mil] "Footprint for Bourns 1140 Inductors with smaller pin Dia."
  round 80 hole 45: 1(-550,0) 2(550,0)
  round 200 hole 150: 11(0,0)
  silkscreen extent -750,-750 750,750
SC70 [mm] "SC-70; 6 Leads"
  rect 0.45x1.25 smd: 1(-0.65,-0.95) 2(0,-0.95) 3(0.65,-0.95) 4(0.65,0.95) 5(0,0.95) 6(-0.65,0.95)
  silkscreen extent -1.28,-1.95 1.15,0.7, body extent -1.1,-1.2 1.1,1.2, height 1.1
SL_5_08HC_180B_02 [mil] "OMNIMATE Signal - Serie BL/SL 5.08  SL 5.08HC/02/180B 3.2"
  rect 100x100 hole 62: 1(-100,0)
  round 100 hole 62: 2(100,0)
  silkscreen extent -235,-149 235,182, body extent -235,-149 235,182, height 473
SMD_LED [mil]
  rect 51.18x62.99 smd: 1(-35,-15) 2(90,-15)
  silkscreen extent 0,15 50,55
SMT_TP [mil] "5016 Surface Mount Test Point"
  rect 185x135 smd: 1(0,0)
SO-G3/C2.25 [mm] "SOT-23; 3 Leads; Body 3.0 x 2.5 mm, inc. leads (LxW max)"
  rect 0.95x1 smd: 1(-0.95,-1.125) 2(0.95,-1.125) 3(0,1.125)
  silkscreen extent -2.1,-1.25 1.32,1.13, body extent -1.45,-1.4 1.45,1.4, height 1.3
TBLOCK-5.08-2 [mil] "Terminal Block, 5.08mm, 2pin"
  rect 100x100 hole 62: 1(-100,0)
  round 100 hole 62: 2(100,0)
  silkscreen extent -200,-160 200,160, body extent -263,-393 263,80, height 334
TBLOCK-5.08-4 [mil] "Terminal Block, 5.08mm, 4pin"
  rect 100x100 hole 62: 1(-300,0)
  round 100 hole 62: 2(-100,0) 3(100,0) 4(300,0)
  silkscreen extent -400,-160 400,160, body extent -463,-392 463,81, height 334
TDK-Lambda [mm] "Power Supply"
  rect 2.2x2.2 hole 1.45 paste-1000 mask+0: 1(19,30.4)
  round 2.2 hole 1.45 paste-1000 mask+0: 2(11.4,30.4) 3(3.8,30.4) 5(7.6,2.5) 6(11.4,2.5) 7(15.2,2.5) 32(2.5,10.1) 33(2.5,6.3) 34(15.2,30.4)
  round 3.05 hole 2 paste-1000 mask+0: 4(3.8,2.5) 8(19,2.5)
  silkscreen extent -0.35,-0.3 23.05,33.92, body extent -0.45,-0.4 23.15,33.3, height 0.25
TO-220-5B [mm] "TO, Thru-Hole, Vertical, Heatsink Mounted; 5 Bent Staggered Leads; Pitch 1.7 mm"
  rect 1.7x1.7 hole 1.1: 1(-3.4,-2)
  round 1.7 hole 1.1: 2(-1.7,2) 3(0,-2) 4(1.7,2) 5(3.4,-2)
  silkscreen extent -5.3,1.53 5.3,6.23, body extent -5.08,-2.17 5.08,5.58, height 19.4

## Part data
+3.3V +5V +12V GND: "PCB Testpoint", Digikey Part Number=36-5016CT-ND
C1 C5 C8 C9 C10 C13 C15 C17 C21 C25 C34 C35 C37 C38 C39 C40 C43: library part ChipElectrolyte, "Electrolyte capacitor, surface mount", Tolerance=20%, Voltage Rating=25V
C2 C3 C4 C6 C7 C14 C16 C18 C19 C22 C23 C26 C27 C29 C30 C31 C32 C33 C36 C41 C44: library part ChipCap, "Capacitor, surface mount", Tolerance=10%
C11 C12 C20 C24 C28 C42: library part CapRadial, "Electrolyte capacitor, leaded, radial", Manufacturer=Nichicon, Tolerance=20%
D1 D2 D4: "Typical RED, GREEN, YELLOW, AMBER GaAs LED", Digikey Part Number=L62305CT-ND
F1: library part CMP-08604-000022-1, "FUSE HOLDER BLADE 80V PCB", Manufacturer=Littelfuse, Package=178.6165, Voltage Rating Ac=80V
J2 J9: library part CMP-02766-000066-1, "CONN HEADER VERT 8POS 2.54MM", Current Rating=6.3A, Manufacturer=Samtec, Temperature="-55°C to +125°C", Temperature Range High=+125°C, Temperature Range Low=-55°C, Voltage Rating=550V
L1 L2 L4 L5 L6 L7 L8 L9 L10: library part MSS1278, "Power inductor, MSS1278 series"
L3 L12: library part Inductor, "Inductor"
LOGO1: library part LIGO_logo
MD1 MD2 MD3 MD4: library part TDK-Lambda, "i6A4W020A033V-005-R"
P1 P5: "Terminal block, 5.08mm, 2-Pin", Part Number=281-1297-ND
P2 P3: library part CMP-1502-00585-1, "Male Locking Header WR-WTB, THT, Vertical, pitch 2.54 mm, 1 x 3 position", Contact Resistance=20mOhm, Manufacturer="Wurth Elektronik", Operating Temperature=-40to105degC, Working Voltage=250VAC
P4: "Terminal block, 5.08mm, 4-Pin", Part Number=281-1299-ND
PO1 PO2 PO3 PO4: library part ATX24PIN_MALE, "Header, 12-Pin, Dual row, ATX power, board", Manufacturers Part Number=39-29-9246, Part Number=23-0039299246-ND
PSwIn PSwO1 PSwO2 PSwO3 PSwO4: "Header, 2-Pin", Digikey Part Number=WM2700-ND
Q1 Q2: "FDV301N, Digital FET, N-channel, SOT23", Part Number=FDV301NCT-ND
R1: library part MYRES, Digikey Part Number=PLT1206-500ACT-ND
R2: library part MYRES, Digikey Part Number=541-249FCT-ND
R3 R6 R7 R8 R9 R10 R11 R12 R13 R14 R15 R16 R17 R18 R19 R20 R21 R22 R23 R24 R25 R26 R27 R28 R29 R30 R31 R32 R33 R35 R36 R38 R39 R40 R41 R42 R43: library part ChipRes1, "Resistor, surface mount", Tolerance=1%
R4: library part Res3, "Resistor", Digikey Part Number=541-2245-1-ND
R5: library part CMP-06022-000038-1, "ICL 16 OHM 15% 2A 13MM", Case/Package=Radial, Current Rating=2A, Max Operating Temperature=160°C, Min Operating Temperature=-20°C, Package Quantity=150, Tolerance=15%
U1 U3: "5 Terminal positive LDO regulator, 1.5A 755-BA00DD0WCP-V5E2"
U2: library part CMP-0253-00520-1, "4-Channel Linear Fan-Speed Controller, -40 to 125 degC, 28-Pin QFN (T2855+8), Pb-Free", Generic Part Number=MAX6620
U8: "Divide-by-8 prescaler"
U9: "Divide-by-2 prescaler"

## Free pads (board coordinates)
  round 180 hole 140: 3(-4825,-175) 4(-1460,-175) 5(-660,-175) 6(170,-175) 7(1185,-175) 8(1800,-4300) 9(-1400,-2485) 10(-610,-2485) 11(215,-2485) 12(1185,-2485) 13(-4825,-4300)

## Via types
v1: diameter 50, hole 28, Top Layer to Bottom Layer, tented both sides, 56 vias
v2: diameter 19.68, hole 7.87, Top Layer to Bottom Layer, 9 vias
v3: diameter 50, hole 28, Top Layer to Bottom Layer, 4 vias

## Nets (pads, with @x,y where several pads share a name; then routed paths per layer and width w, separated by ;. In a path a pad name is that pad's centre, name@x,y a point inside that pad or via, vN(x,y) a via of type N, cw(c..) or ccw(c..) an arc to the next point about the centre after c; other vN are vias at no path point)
12FAN: C14.2 C16.2 C42.1 C43.1 C44.1 L12.1 R7.2 R11.2 U1.1 U1.2 U2.26 U3.1 U3.2 | length 1566.3
  Top Layer w10: U2.26 -3467.16,-4005 v1(-3460,-4005)
  Top Layer w20: R11.2 -3646.06,-4262.4 -3630.47,-4277.99 -3630.47,-4294.53 v1(-3600,-4325) -3569.53,-4294.53 -3569.53,-4277.99 -3553.94,-4262.4 R7.2
  Bottom Layer w20: U3.2 -4004.45,-3861.1 -4004.45,-3903.62 -3933.07,-3975 -3700,-3975 -3600,-4075 v1(-3600,-4325)
  Bottom Layer w40: U3.2 -3941.14,-3790.55 U3.1 -3967.05,-3674.09 -3967.05,-3627.64 ; C14.2 C14.2@-3967.05,-3602.64 ; U1.2 -2991.14,-3790.55 U1.1 -3017.05,-3674.09 -3017.05,-3627.64 ; C16.2 C16.2@-3017.05,-3602.64
24PWR: C5.1 C17.1 C21.1 C25.1 L1.1 L2.1 L6.1 L7.1 L8.1 | length 6594
  Bottom Layer w60: L1.1 C5.1 ; L6.1 C17.1 ; L7.1 C25.1 ; L8.1 C21.1
  Bottom Layer w150: L1.1 L6.1 L7.1 L8.1 1342,-3833 1625,-3550 L2.1
24VIN: L2.2 R5.1 | length 319.2
  Bottom Layer w100: L2.2 1647.99,-910.01 1647.99,-799.65 R5.1
32768Hz: R30.2 U8.6 | length 2770.7
  Top Layer w10: v1(-3800,-3425) -3800,-3300 -2374.41,-1874.41 -2374.41,-1800 U8.6
  Bottom Layer w10: R30.2 v1(-3800,-3425) v1@-3800,-3420
262144Hz: R35.1 R36.2 U8.3 | length 262.3
  Top Layer w10: R36.2 -2567.6,-1083.94 -2547.01,-1104.53 -2543.07,-1104.53 -2500,-1147.6 R35.1 U8.3
+3.3V: +3.3V.1 C3.2 C11.1 C20.1 C29.2 C30.2 C31.2 L4.2 L5.2 MD1.7 MD2.7 PO1.1 PO1.2 PO1.12 PO1.13 PO2.1 PO2.2 PO2.12 PO2.13 PO3.1 PO3.2 PO3.12 PO3.13 PO4.1 PO4.2 PO4.12 PO4.13 R2.2 R3.1 R14.1 R15.1 R16.2 R32.2 R38.2 R39.2 U2.27 U8.4 U9.4 | length 3150.8
  Top Layer w10: U2.27 -3487.39,-3956.93 -3448.07,-3956.93 v1(-3400,-4005) ; v3(-2650,-1375) -2625,-1350 U9.4@-2625,-1310 ; v3(-2450,-1375) -2425,-1350 U8.4@-2425,-1310
  Top Layer w30: R15.1@-2450,-4290 R15.1 v1(-2450,-4225) ; R16.2 -2352.01,-889.41 -2352.01,-877.01 v1(-2300,-825) -2247.99,-877.01 -2247.99,-889.41 R3.1 ; R14.1 v1(-2325,-3005) ; L5.2@-950,-2877 L5.2 ; v1(1100,-1525) +3.3V.1 1225,-1508.18 1277.5,-1455.68 1319.32,-1455.68 R2.2
  Top Layer w60: MD1.7 -1899,-3150.97 -1899,-2876 L4.2 -1650,-2850 C11.1 ; MD2.7 -950,-3151.97 L5.2@-950,-2877 ; L5.2 -700,-2850 C20.1
  Bottom Layer w20: v1(-3400,-4005) -3400,-3952.4 R32.2 ; R38.2 v1(-3395,-3425) ; R39.2 v1(-3315,-3425)
  Bottom Layer w30: MD1.7 -1974.61,-3223.99 -1933.46,-3182.85 C3.2 ; MD2.7 -1024.61,-3223.99 -983.46,-3182.85 C29.2
  Bottom Layer w60: C31.2 -1673.5,-2881.61 -1618.39,-2881.61 C11.1 ; C30.2 -723.5,-2881.61 -668.39,-2881.61 C20.1
+5V: +5V.1 C24.1 C26.2 C32.2 L9.2 MD3.7 P4.4 PO1.4 PO1.6 PO1.21 PO1.22 PO1.23 PO2.4 PO2.6 PO2.21 PO2.22 PO2.23 PO3.4 PO3.6 PO3.21 PO3.22 PO3.23 PO4.4 PO4.6 PO4.21 PO4.22 PO4.23 R1.2 R24.1 R25.1 R26.1 R27.1 | length 2301.9
  Top Layer w30: L9.2@0,-2877 L9.2 ; PO4.21 584.8,-1850 +5V.1 1225,-1833.18 1277.5,-1780.68 1319.32,-1780.68 R1.2
  Top Layer w60: MD3.7 0,-3151.97 L9.2@0,-2877 ; L9.2 255,-2850 C24.1
  Bottom Layer w20: PO1.21 R27.1 ; PO2.21 R26.1 ; PO3.21 R24.1 ; PO4.21 R25.1
  Bottom Layer w30: MD3.7 -74.61,-3223.99 -33.46,-3182.85 C26.2
  Bottom Layer w60: C32.2 226.5,-2881.61 286.61,-2881.61 C24.1
+5VSB1: PO1.9 R27.2 | length 76.5
  Bottom Layer w20: R27.2 PO1.9
+5VSB2: PO2.9 R26.2 | length 76.5
  Bottom Layer w20: R26.2 PO2.9
+5VSB3: PO3.9 R24.2 | length 71.5
  Bottom Layer w20: R24.2 PO3.9
+5VSB4: PO4.9 R25.2 | length 71.5
  Bottom Layer w20: R25.2 PO4.9
+12V: +12V.1 C27.2 C28.1 C33.2 L3.1 L10.2 MD4.7 P4.1 P5.1 PO1.10 PO1.11 PO2.10 PO2.11 PO3.10 PO3.11 PO4.10 PO4.11 R4.1 | length 11516.3
  Top Layer w20: 977,-2177 979,-2175
  Top Layer w30: L10.2@950,-2877 L10.2 ; 979,-2175 +12V.1 1225,-2158.18 1277.5,-2105.68 1319.32,-2105.68 R4.1
  Top Layer w60: MD4.7 950,-3151.97 L10.2@950,-2877
  Top Layer w64: PO1.11 -1700,-2005 ; PO1.10 -1700,-2005 ; PO2.11 -890,-2005 ; PO2.10 -890,-2005 ; PO3.11 -100,-2005 ; PO3.10 -100,-2005 ; PO4.11 710,-2005 ; PO4.10 710,-2005 ; C28.1 1200,-2850 L10.2 977,-2177 805,-2005 710,-2005 ; -1700,-2005 -890,-2005 ; -890,-2005 -100,-2005 ; -100,-2005 710,-2005
  Bottom Layer w30: MD4.7 875.39,-3223.99 916.54,-3182.85 C27.2
  Bottom Layer w60: L3.1 -2495,-2005 -1700,-2005 ; PO1.11 -1700,-2005 ; PO1.10 -1700,-2005 ; PO2.11 -890,-2005 ; PO2.10 -890,-2005 ; PO3.11 -100,-2005 ; PO3.10 -100,-2005 ; PO4.11 710,-2005 ; PO4.10 710,-2005 ; C33.2 1373.91,-2881.61 1318.39,-2881.61 C28.1 1275,-2924.79 1200.21,-2850 1044.6,-2850 977.36,-2782.76 977.36,-2177.36 805,-2005 710,-2005 ; -1700,-2005 -890,-2005 ; -890,-2005 -100,-2005 ; -100,-2005 710,-2005
FANCLK: R33.2 R36.1 U9.3 | length 348.7
  Top Layer w10: R33.2 R36.1 -2642.4,-1212.13 -2636.54,-1217.99 -2629.45,-1217.99 -2625.59,-1221.85 U9.3
FF: R32.1 U2.28 | length 131.1
  Top Layer w10: U2.28 -3469.85,-3907.65 -3457.65,-3907.65 v1(-3450,-3900)
  Bottom Layer w20: v1(-3450,-3900) -3445.1,-3900 -3423.28,-3878.19 -3400.59,-3878.19 R32.1
GND: C1.2 C2.1 C3.1 C4.1 C5.2 C6.1 C7.1 C8.2 C9.2 C10.2 C11.2 C12.2 C13.2 C14.1 C15.2 C16.1 C17.2 C18.1 C19.1 C20.2 C21.2 C22.1 C23.1 C24.2 C25.2 C26.1 C27.1 C28.2 C29.1 C30.1 C31.1 C32.1 C33.1 C34.2 C35.2 C36.2 C37.2 C38.2 C39.2 C40.2 C41.2 C42.2 C43.2 C44.2 D1.2 D2.2 D4.2 GND.1 J2.1 J2.3 J2.5 J2.7 MD1.3 MD1.4 MD2.3 MD2.4 MD2.33 MD3.3 MD3.4 MD4.3 MD4.4 MD4.33 P1.2 P2.1 P3.1 P4.2 P4.3 P5.2 PO1.3 PO1.5 PO1.7 PO1.15 PO1.17 PO1.18 PO1.19 PO1.24 PO2.3 PO2.5 PO2.7 PO2.15 PO2.17 PO2.18 PO2.19 PO2.24 PO3.3 PO3.5 PO3.7 PO3.15 PO3.17 PO3.18 PO3.19 PO3.24 PO4.3 PO4.5 PO4.7 PO4.15 PO4.17 PO4.18 PO4.19 PO4.24 Q1.2 Q2.2 R8.1 R12.1 R17.2 R18.2 R19.2 R20.2 R23.1 R31.2 R40.1 R41.1 R42.1 R43.1 U1.3 U2.4 U2.10 U2.11 U2.18 U2.25 U2.29 U3.3 U8.2 U8.5 U9.2 U9.5 | length 5804.7
  Top Layer w10: U2.18 v2(-3630.62,-3930.62) v2(-3600,-3900) ; U2.11 v2(-3630.62,-3869.38) v2(-3600,-3900) ; U2.10 -3600,-3872.16 v2(-3600,-3900) ; U2.25 v2(-3569.38,-3930.62) v2(-3600,-3900) ; U2.4 v2(-3569.38,-3869.38) v2(-3600,-3900)
  Top Layer w14: U9.5 U9.2 v3(-2600,-1175) ; U8.5 U8.2 v3(-2400,-1175)
  Top Layer w20: v1(-3850,-4225) R12.1@-3850,-4162.4 ; v1(-3350,-4215) R8.1 ; v1(-2475,-725) -2471.96,-721.96 -2471.96,-690.26 -2447.09,-665.39 -2446.1,-665.39 -2437.4,-656.69 Q1.2 ; v1(-2275,-725) -2271.96,-721.96 -2271.96,-690.26 -2247.09,-665.39 -2246.1,-665.39 -2237.4,-656.69 Q2.2
  Top Layer w30: v1(-2350,-4225) -2350,-4285 R23.1@-2345,-4290 ; v1(1100,-1200) GND.1 ; D4.2 v1(1850,-2025) ; D1.2 v1(1850,-1700) ; D2.2 v1(1850,-1375)
  Bottom Layer w20: R31.2 v2(-3661.25,-3900) ; v1(-3720,-3425) -3720,-3485 -3717.4,-3487.6 R41.1 ; R41.1@-3637.6,-3487.6 R43.1 R40.1 v1(-3475,-3425)
  Bottom Layer w30: C2.1 v1(-2030,-3125) ; C4.1 v1(-2005,-3025) ; C3.1 v1(-1805,-3125) ; R17.2 -1637.6,-3128.94 -1627.01,-3139.53 -1612.83,-3139.53 MD1.4 ; C6.1 v1(-1080,-3125) ; C7.1 v1(-1055,-3025) ; C29.1 v1(-855,-3125) ; R18.2 -687.6,-3128.94 -677.01,-3139.53 -662.83,-3139.53 MD2.4 ; C18.1 v1(-130,-3125) ; C19.1 v1(-105,-3025) ; C26.1 v1(95,-3125) ; R19.2 262.4,-3128.94 272.99,-3139.53 287.17,-3139.53 MD3.4 ; C22.1 v1(820,-3125) ; C23.1 v1(845,-3025) ; C27.1 v1(1045,-3125) ; R20.2 1212.4,-3128.94 1222.99,-3139.53 1237.16,-3139.53 MD4.4
  Bottom Layer w40: U3.3 -4075,-3692.71 -4049.09,-3666.81 -4049.09,-3627.64 ; C14.1@-4049.09,-3602.64 C14.1 ; U1.3 -3125,-3692.71 -3099.09,-3666.81 -3099.09,-3627.64 ; C16.1@-3099.09,-3602.64 C16.1
  Bottom Layer w50: v1(-4325,-4075) C15.2 ; C13.2 v1(-2875,-4075)
  Bottom Layer w60: C31.1 -1673.5,-2768.39 -1615.24,-2768.39 C11.2 ; MD1.3 -1525,-4325 -1276.69,-4076.69 -1276.69,-4076.5 -1275.2,-4075 C1.2 ; C30.1 -723.5,-2768.39 -665.24,-2768.39 C20.2 ; MD2.3 -575,-4325 -326.69,-4076.69 -326.69,-4076.5 -325.2,-4075 C8.2 ; C32.1 226.5,-2768.39 279.76,-2768.39 C24.2 ; MD3.3 375,-4325 623.31,-4076.69 623.31,-4076.5 624.8,-4075 C9.2 ; C28.2 1315.24,-2768.39 1373.91,-2768.39 C33.1 ; MD4.3 1325,-4325 1573.31,-4076.69 1573.31,-4076.5 1574.8,-4075 C10.2
  other v1: -1899,-3325 -1750,-3325 -950,-3325 -800,-3325 0,-3325 150,-3325 950,-3325 1100,-3325
  other v2: -3600,-3961.25 -3538.75,-3900 -3600,-3838.75
NetC1_1: C1.1 L1.2 MD1.1 | length 760.6
  Bottom Layer w60: MD1.1 -2014.21,-4215 -1873,-4215 L1.2 -1795,-4167 -1746.5,-4118.5 -1746.5,-4110.15 -1711.35,-4075 C1.1
NetC2_2: C2.2 C4.2 L4.1 MD1.8 | length 635.6
  Top Layer w100: L4.1 -2207,-3143.79 MD1.8
  Bottom Layer w60: C4.2 -2180.12,-3125 -2180.12,-3163.67 -2124.21,-3219.58 MD1.8
NetC6_2: C6.2 C7.2 L5.1 MD2.8 | length 635.6
  Top Layer w100: L5.1 -1257,-3143.79 MD2.8
  Bottom Layer w60: C7.2 -1230.12,-3125 -1230.12,-3163.67 -1174.21,-3219.58 MD2.8
NetC8_1: C8.1 L6.2 MD2.1 | length 760.6
  Bottom Layer w60: MD2.1 -1064.21,-4215 -923,-4215 L6.2 -845,-4167 -796.5,-4118.5 -796.5,-4110.15 -761.35,-4075 C8.1
NetC9_1: C9.1 L7.2 MD3.1 | length 760.6
  Bottom Layer w60: MD3.1 -114.21,-4215 27,-4215 L7.2 105,-4167 153.5,-4118.5 153.5,-4110.15 188.65,-4075 C9.1
NetC10_1: C10.1 L8.2 MD4.1 | length 760.6
  Bottom Layer w60: MD4.1 835.79,-4215 977,-4215 L8.2 1055,-4167 1103.5,-4118.5 1103.5,-4110.15 1138.65,-4075 C10.1
NetC12_1: C12.1 C34.1 C35.1 C36.1 C37.1 C38.1 C39.1 C40.1 C41.1 L3.2 L12.2
NetC13_1: C13.1 P2.2 U1.4 U2.23 | length 984.6
  Top Layer w10: U2.23 -3520,-4035.68 v1(-3520,-4075)
  Top Layer w20: U1.4 -3125,-3924.41 v1(-3125,-4075) P2.2
  Bottom Layer w20: v1(-3520,-4075) C13.1 v1(-3125,-4075)
NetC15_1: C15.1 P3.2 U2.20 U3.4 | length 984.6
  Top Layer w10: v1(-3680,-4075) -3680,-4035.68 U2.20
  Top Layer w20: U3.4 -4075,-3924.41 v1(-4075,-4075) P3.2
  Bottom Layer w20: v1(-4075,-4075) C15.1 v1(-3680,-4075)
NetC18_2: C18.2 C19.2 L9.1 MD3.8 | length 635.6
  Top Layer w100: L9.1 -307,-3143.79 MD3.8
  Bottom Layer w60: C19.2 -280.12,-3163.67 -224.21,-3219.58 MD3.8
NetC22_2: C22.2 C23.2 L10.1 MD4.8 | length 635.6
  Top Layer w100: L10.1 643,-3143.79 MD4.8
  Bottom Layer w60: C23.2 669.88,-3163.67 725.79,-3219.58 MD4.8
NetD1_1: D1.1 R1.1 | length 115
  Top Layer w30: R1.1 D1.1
NetD2_1: D2.1 R2.1 | length 115
  Top Layer w30: R2.1 D2.1
NetD4_1: D4.1 R4.2 | length 115
  Top Layer w30: R4.2 D4.1
NetJ9_1: J9.1 J9.3 Q1.1 | length 245.9
  Top Layer w10: J9.1 -2405,-525 -2400,-530 ; Q1.1 -2362.6,-654.72 -2376.3,-641.02 -2377.28,-641.02 -2400,-618.31 -2400,-530 ; J9.3 -2395,-525 -2400,-530
NetJ9_5: J9.5 J9.7 Q2.1 | length 245.9
  Top Layer w10: J9.5 -2205,-525 -2200,-530 ; Q2.1 -2162.6,-654.72 -2176.3,-641.02 -2177.28,-641.02 -2200,-618.31 -2200,-530 ; J9.7 -2195,-525 -2200,-530
NetMD1_6: MD1.6 R17.1 | length 157
  Bottom Layer w30: MD1.6 -1737.95,-3139.53 -1722.99,-3139.53 -1712.4,-3128.94 R17.1
NetMD1_32: MD1.32 MD2.32 R21.2 | length 4262.3
  Top Layer w10: R21.2 -2237.4,-1078.94 -2257.99,-1099.53 -2261.93,-1099.53 -2275,-1112.6 -2275,-1975 -2400,-2100 -2400,-3275 -2300,-3375 -1625,-3375 -1474.6,-3525.4 MD1.32 ; MD1.32@-1474.21,-3525.79 MD2.32
  Bottom Layer w30: MD1.32@-1488.1,-3525.79 MD1.32
NetMD2_6: MD2.6 R18.1 | length 157
  Bottom Layer w30: MD2.6 -787.95,-3139.53 -772.99,-3139.53 -762.4,-3128.94 R18.1
NetMD3_6: MD3.6 R19.1 | length 157
  Bottom Layer w30: MD3.6 162.05,-3139.53 177.01,-3139.53 187.6,-3128.94 R19.1
NetMD3_32: MD3.32 MD4.32 R22.2 | length 6332
  Top Layer w10: R22.2 -2362.6,-1078.94 -2342.01,-1099.53 -2338.07,-1099.53 -2325,-1112.6 -2325,-1925 -2475,-2075 -2475,-3300 -2310.39,-3464.61 -1685.39,-3464.61 -1525,-3625 325,-3625 424.21,-3525.79 MD3.32 1374.21,-3525.79 MD4.32@1375,-3525
  Bottom Layer w30: MD3.32@424.45,-3525.79 MD3.32
NetMD4_6: MD4.6 R20.1 | length 157
  Bottom Layer w30: MD4.6 1039.96,-3226.57 1127.01,-3139.53 1137.6,-3128.94 R20.1
NetP1_1: P1.1 R5.2 | length 477.6
  Bottom Layer w100: R5.2 1725,-427.36 P1.1
NetP2_3: P2.3 R28.1 | length 364.5
  Top Layer w20: R28.1 -3090,-4390 P2.3
NetP3_3: P3.3 R29.1 | length 164.5
  Top Layer w20: P3.3 -3910,-4390 R29.1
NetQ1_3: Q1.3 R16.1 R22.1 R33.1 | length 477
  Top Layer w10: R33.1 R16.1 ; R22.1 R16.1 ; Q1.3 -2400,-745.28 -2413.7,-758.98 -2414.69,-758.98 -2437.4,-781.69 R16.1
NetQ2_3: Q2.3 R3.2 R21.1 | length 346.8
  Top Layer w10: Q2.3 -2200,-745.28 -2186.3,-758.98 -2185.31,-758.98 -2162.6,-781.69 R21.1
NetR6_1: R6.1 U1.5 | length 216.6
  Top Layer w20: R6.1@-3383.46,-3865 -3365.47,-3847.01 -3365.47,-3843.07 -3265.51,-3743.1 -3265.51,-3706.65 U1.5
NetR6_2: R6.2 R8.2 R9.1 | length 288
  Top Layer w20: R9.1 -3434.41,-4136.81 -3421.81,-4136.81 -3378.19,-4093.19 -3365.59,-4093.19 R8.2 -3350,-3972.4 -3365.47,-3956.93 -3365.47,-3952.99 -3381.06,-3937.4 R6.2
NetR7_1: R7.1 R28.2 U2.22 | length 458.9
  Top Layer w10: U2.22 -3560,-4023.52 -3560,-4180 R7.1@-3550,-4190
  Top Layer w20: R7.1@-3550,-4190 -3540,-4200 -3500,-4200 -3437.4,-4262.6 R28.2
NetR9_2: R9.2 U2.24 | length 138.6
  Top Layer w10: U2.24 -3473.29,-4054.55 R9.2@-3473.29,-4091.71
NetR10_1: R10.1 U3.5 | length 462.3
  Top Layer w20: U3.5 -4133.86,-3775 -3901.54,-3775 -3829.53,-3847.01 R10.1@-3813.94,-3862.6
NetR10_2: R10.2 R12.2 R13.1 | length 286.1
  Top Layer w20: R10.2@-3813.94,-3937.4 -3829.53,-3952.99 -3829.53,-3956.93 -3850,-3977.4 R12.2 -3834.41,-4093.19 -3821.81,-4093.19 -3778.19,-4136.81 -3765.59,-4136.81 R13.1
NetR11_1: R11.1 R29.2 U2.21 | length 460.9
  Top Layer w10: R11.1@-3650,-4190 -3640,-4180 -3640,-4023.52 U2.21
  Top Layer w20: R29.2 -3762.6,-4260.88 -3701.71,-4200 -3662.4,-4200 R11.1
NetR13_2: R13.2 U2.19 | length 135.3
  Top Layer w10: R13.2@-3735,-4085 -3726.71,-4076.71 -3726.71,-4054.55 U2.19
NetR30_1: R30.1 U2.8 | length 344.5
  Top Layer w10: v1(-3770,-3725) -3691.48,-3725 U2.8
  Bottom Layer w20: R30.1 -3800,-3695 v1(-3770,-3725)
NetR31_1: R31.1 U2.9 | length 313.8
  Top Layer w10: v1(-3815,-3775) -3669.32,-3775 U2.9
  Bottom Layer w20: v1(-3815,-3775) -3815,-3892.4 R31.1
NetR35_2: R35.2 U9.6 | length 75.4
  Top Layer w10: U9.6 -2502.4,-1312.4 R35.2@-2500,-1310
NetR38_1: R38.1 U2.2 | length 341.4
  Top Layer w10: U2.2 -3430,-3785.68 v1(-3430,-3725)
  Bottom Layer w20: v1(-3430,-3725) -3395,-3690 R38.1
NetR39_1: R39.1 U2.1 | length 386.5
  Top Layer w10: U2.1 -3391.48,-3775 v1(-3385,-3775)
  Bottom Layer w20: v1(-3385,-3775) -3315,-3705 R39.1
NetR40_2: R40.2 U2.3 | length 300.1
  Top Layer w10: U2.3 -3490,-3817.84 v1(-3490,-3680)
  Bottom Layer w20: v1(-3490,-3680) -3490,-3577.4 R40.2
NetR41_2: R41.2 U2.6 | length 287.6
  Top Layer w10: v1(-3635,-3665) -3543,-3757 -3543,-3787.32 U2.6
  Bottom Layer w20: R41.2 -3635,-3567.4 v1(-3635,-3665)
NetR42_2: R42.2 U2.7 | length 304.2
  Top Layer w10: v1(-3710,-3680) -3705.62,-3684.38 -3677.81,-3684.38 U2.7
  Bottom Layer w20: R42.2 -3710,-3572.4 v1(-3710,-3680)
NetR43_2: R43.2 U2.5 | length 285.9
  Top Layer w10: v1(-3565,-3665) -3520,-3710 -3520,-3792.16 U2.5
  Bottom Layer w20: v1(-3565,-3665) -3565,-3567.4 R43.2
ON/OFF: MD1.2 MD2.2 MD3.2 MD4.2 R15.2 R23.2 | length 3864
  Top Layer w20: R15.2 -2400,-4362.4 ; R23.2@-2350,-4365 -2352.6,-4362.4 -2400,-4362.4 ; MD1.2 -1925,-4425 -2375,-4425 -2400,-4400 -2400,-4362.4
  Bottom Layer w20: MD1.2 -1725,-4425 -975,-4425 MD2.2 -775,-4425 -25,-4425 MD3.2 175,-4425 925,-4425 MD4.2
PG: MD1.5 MD2.5 MD3.5 MD4.5 PO1.8 PO2.8 PO3.8 PO4.8 R14.2 | length 8381.5
  Top Layer w10: R14.2 -2325,-3251.6 -2274.98,-3301.61 -2093.13,-3301.61 -2076.52,-3285 -1733.8,-3285 MD1.5 MD1.5@-1675.38,-3227.45 ; PO4.8@710,-1593.88 PO4.8 627.8,-1675 -17.8,-1675 PO3.8 -182.2,-1675 -807.8,-1675 PO2.8 -972.2,-1675 -1617.8,-1675 PO1.8 -1805,-1697.8 -1805,-2345.79 -1450,-2700.79 -1450,-3002.07 MD1.5@-1675.38,-3227.45 ; MD4.5 1116.31,-3284.88 773.6,-3284.88 756.87,-3301.61 299.65,-3301.61 MD3.5 166.2,-3285 -176.52,-3285 -193.13,-3301.61 -650.35,-3301.61 MD2.5 -783.8,-3285 -1126.52,-3285 -1143.13,-3301.61 -1601.22,-3301.61 -1612.83,-3290 MD1.5@-1675.38,-3227.45
PS-ON: PO1.16 PO2.16 PO3.16 PO4.16 | length 2611.8
  Top Layer w20: PO1.16 -1835.8,-850 -1188.2,-850 PO2.16 -1025.8,-850 -398.2,-850 PO3.16 -235.8,-850 411.8,-850 PO4.16
PWR+: PSwIn.1 PSwO1.1 PSwO2.1 PSwO3.1 PSwO4.1 | length 1825
  Top Layer w30: PSwIn.1 PSwO1.1 -3130,430 -3180,430 -3405,430 -3445,430 -3555,430 ; -3980,430 PSwO3.1@-3745,430 ; -3980,430 PSwO3.1@-3745,430 ; -3980,430 PSwO4.1 -3980,430 ; PSwO3.1@-3745,430 -3555,430 ; PSwO3.1@-3745,430 -3555,430
PWR-: PSwIn.2 PSwO1.2 PSwO2.2 PSwO3.2 PSwO4.2 | length 1839.1
  Top Layer w30: PSwIn.2 PSwO1.2 -3130,330 -3180,330 -3405,330 -3445,330 -3555,330 ; -3980,330 PSwO4.2 -3980,330 ; -3980,330 PSwO3.2@-3745,330 ; -3980,330 PSwO3.2@-3745,330 ; PSwO3.2@-3745,330 -3555,330 ; PSwO3.2@-3745,330 -3555,330
  Bottom Layer w30: PSwO4.2 PSwO4.2@-4070,320
SYNC0: J2.2 J9.2 | length 291.4
  Top Layer w10: J9.2 -2400,-375 -2400,-225 J2.2
SYNC1: J2.4 J9.4 | length 291.4
  Top Layer w10: J9.4 -2300,-375 -2300,-225 J2.4
SYNC2: J2.6 J9.6 | length 291.4
  Top Layer w10: J9.6 -2200,-375 -2200,-225 J2.6
SYNC3: J2.8 J9.8 | length 291.4
  Top Layer w10: J9.8 -2100,-375 -2100,-225 J2.8
pads on no net: F1. F1.1 F1.2 L3.11 L12.11 MD1.33 MD1.34 MD2.34 MD3.33 MD3.34 MD4.34 PO1.14 PO1.20 PO1.25 PO1.26 PO2.14 PO2.20 PO2.25 PO2.26 PO3.14 PO3.20 PO3.25 PO3.26 PO4.14 PO4.20 PO4.25 PO4.26 U2.12 U2.13 U2.14 U2.15 U2.16 U2.17 U8.1 U9.1

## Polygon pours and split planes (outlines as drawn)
GND on Int1 GND (split plane): 1979.9,-4479.9 -5979.9,-4479.9 -5979.9,-20.1 1979.9,-20.1
+3.3V on Int2 PWR (split plane): 1979.9,-4479.9 -5979.9,-4479.9 -5979.9,-20.1 1979.9,-20.1
GND on Int3 GND (split plane): 1979.9,-4479.9 -5979.9,-4479.9 -5979.9,-20.1 1979.9,-20.1
+5V on Int4 PWR (split plane): 1979.9,-4479.9 -2504.9,-4479.9 -2504.9,-1650 -2505.29,-1646.08 -2506.43,-1642.31 -2508.29,-1638.83 -2510.79,-1635.79 -3560.79,-585.79 -3563.83,-583.29 -3567.31,-581.43 -3571.08,-580.29 -3575,-579.9 -5979.9,-579.9 -5979.9,-20.1 1979.9,-20.1
12FAN on Int4 PWR (split plane): -2545.1,-1658.32 -2545.1,-4479.9 -5979.9,-4479.9 -5979.9,-620.1 -3583.32,-620.1

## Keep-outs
Keep-Out Layer:
  lines w5: -5000,-4500 1975,-4500 2000,-4500 2000,0 -5000,0 -5000,-4500

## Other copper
Bottom Layer:
  rectangle net 12FAN: -2775,-3175 -2575,-2945
  rectangle net NetC12_1: -2775,-2805 -2575,-2575
  rectangle net GND: -1925,-3350 -1725,-3300
  rectangle net GND: -975,-3350 -775,-3300
  rectangle net GND: -25,-3350 175,-3300
  rectangle net GND: 925,-3350 1125,-3300
Int4 PWR (plane layer: these items are gaps in the copper):
  lines w40: -6000,-2025 -6000,-600 -3575,-600 -2525,-1650 -2525,-4500 -2625,-4500

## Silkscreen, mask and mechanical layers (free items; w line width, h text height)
Top Overlay:
  region: 1925,-2825 1525,-2825 1525,-4125 1925,-4125
  lines w5: -6002.5,-4500 -6002.5,-0.02 ; -6000,-4500 1999.98,-4500 1999.98,-0.02 -4999.98,-0.02 -6000,-0.02
  text "IO Chassis Power Fanout" at -4590,-280 h70
  text "aLIGO D1800033-v3" at -4590,-390 h70
  text "+3.3V" at 1480,-1520 h70
  text "+5V" at 1610,-1845 h70
  text "+12V" at 1550,-2170 h70
  text "S/N" at 1660,-2535 h90 r270
Bottom Overlay:
  circle w100: c1795,1100 r160
  circle w60: c1800,-4300 r130
  circle w60: c1185,-2485 r130
  circle w60: c215,-2485 r130
  circle w60: c-610,-2485 r130
  circle w60: c-1400,-2485 r130
  circle w60: c1185,-175 r130
  circle w60: c170,-175 r130
  circle w60: c-660,-175 r130
  circle w60: c-1460,-175 r130
  circle w60: c-4825,-4300 r130
  circle w60: c-4825,-175 r130
  circle w100: c-2400,1440 r160
Mechanical 1:
  lines w5: -5000,-4500 -5000,0 2000,0 2000,-4500 -5000,-4500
